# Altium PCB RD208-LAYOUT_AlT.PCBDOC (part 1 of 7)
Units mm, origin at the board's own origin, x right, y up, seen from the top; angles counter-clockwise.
Board outline 240 x 150 mm, 6 copper layers (TOP, Mid-Layer 1, Mid-Layer 2, Mid-Layer 3, Mid-Layer 4, BOTTOM), stack 1.422 mm thick; 773 components, 409 nets, 3936 pads, 97 vias.
Unrouted connection lines stored in the file: 1.
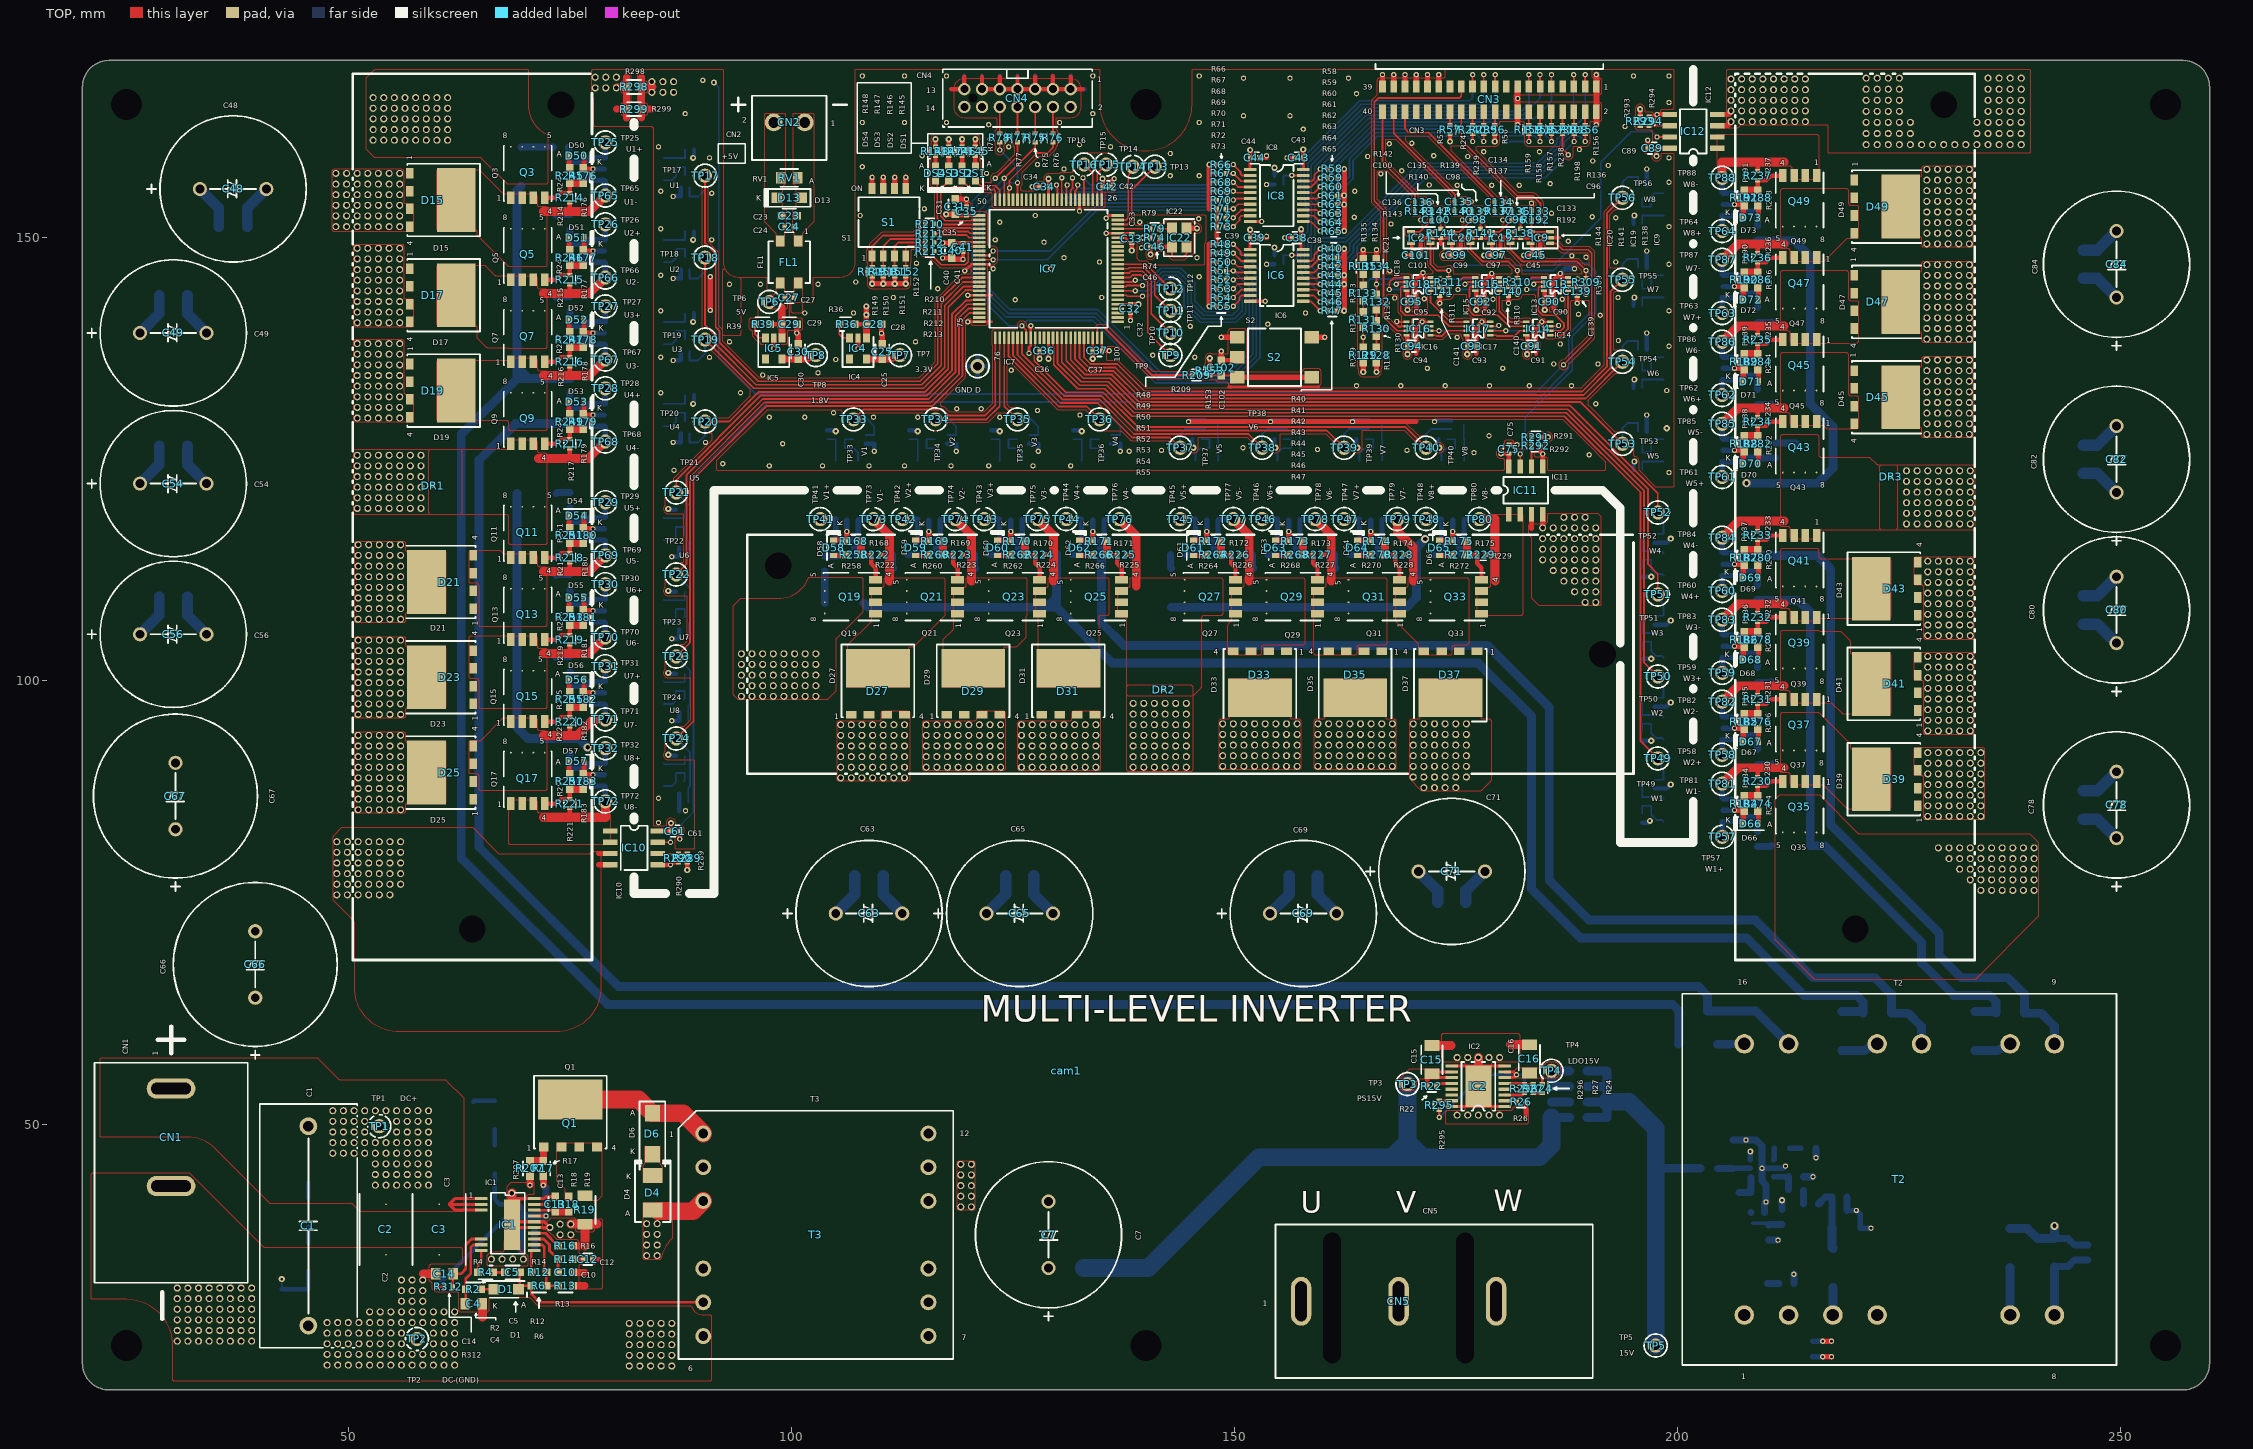
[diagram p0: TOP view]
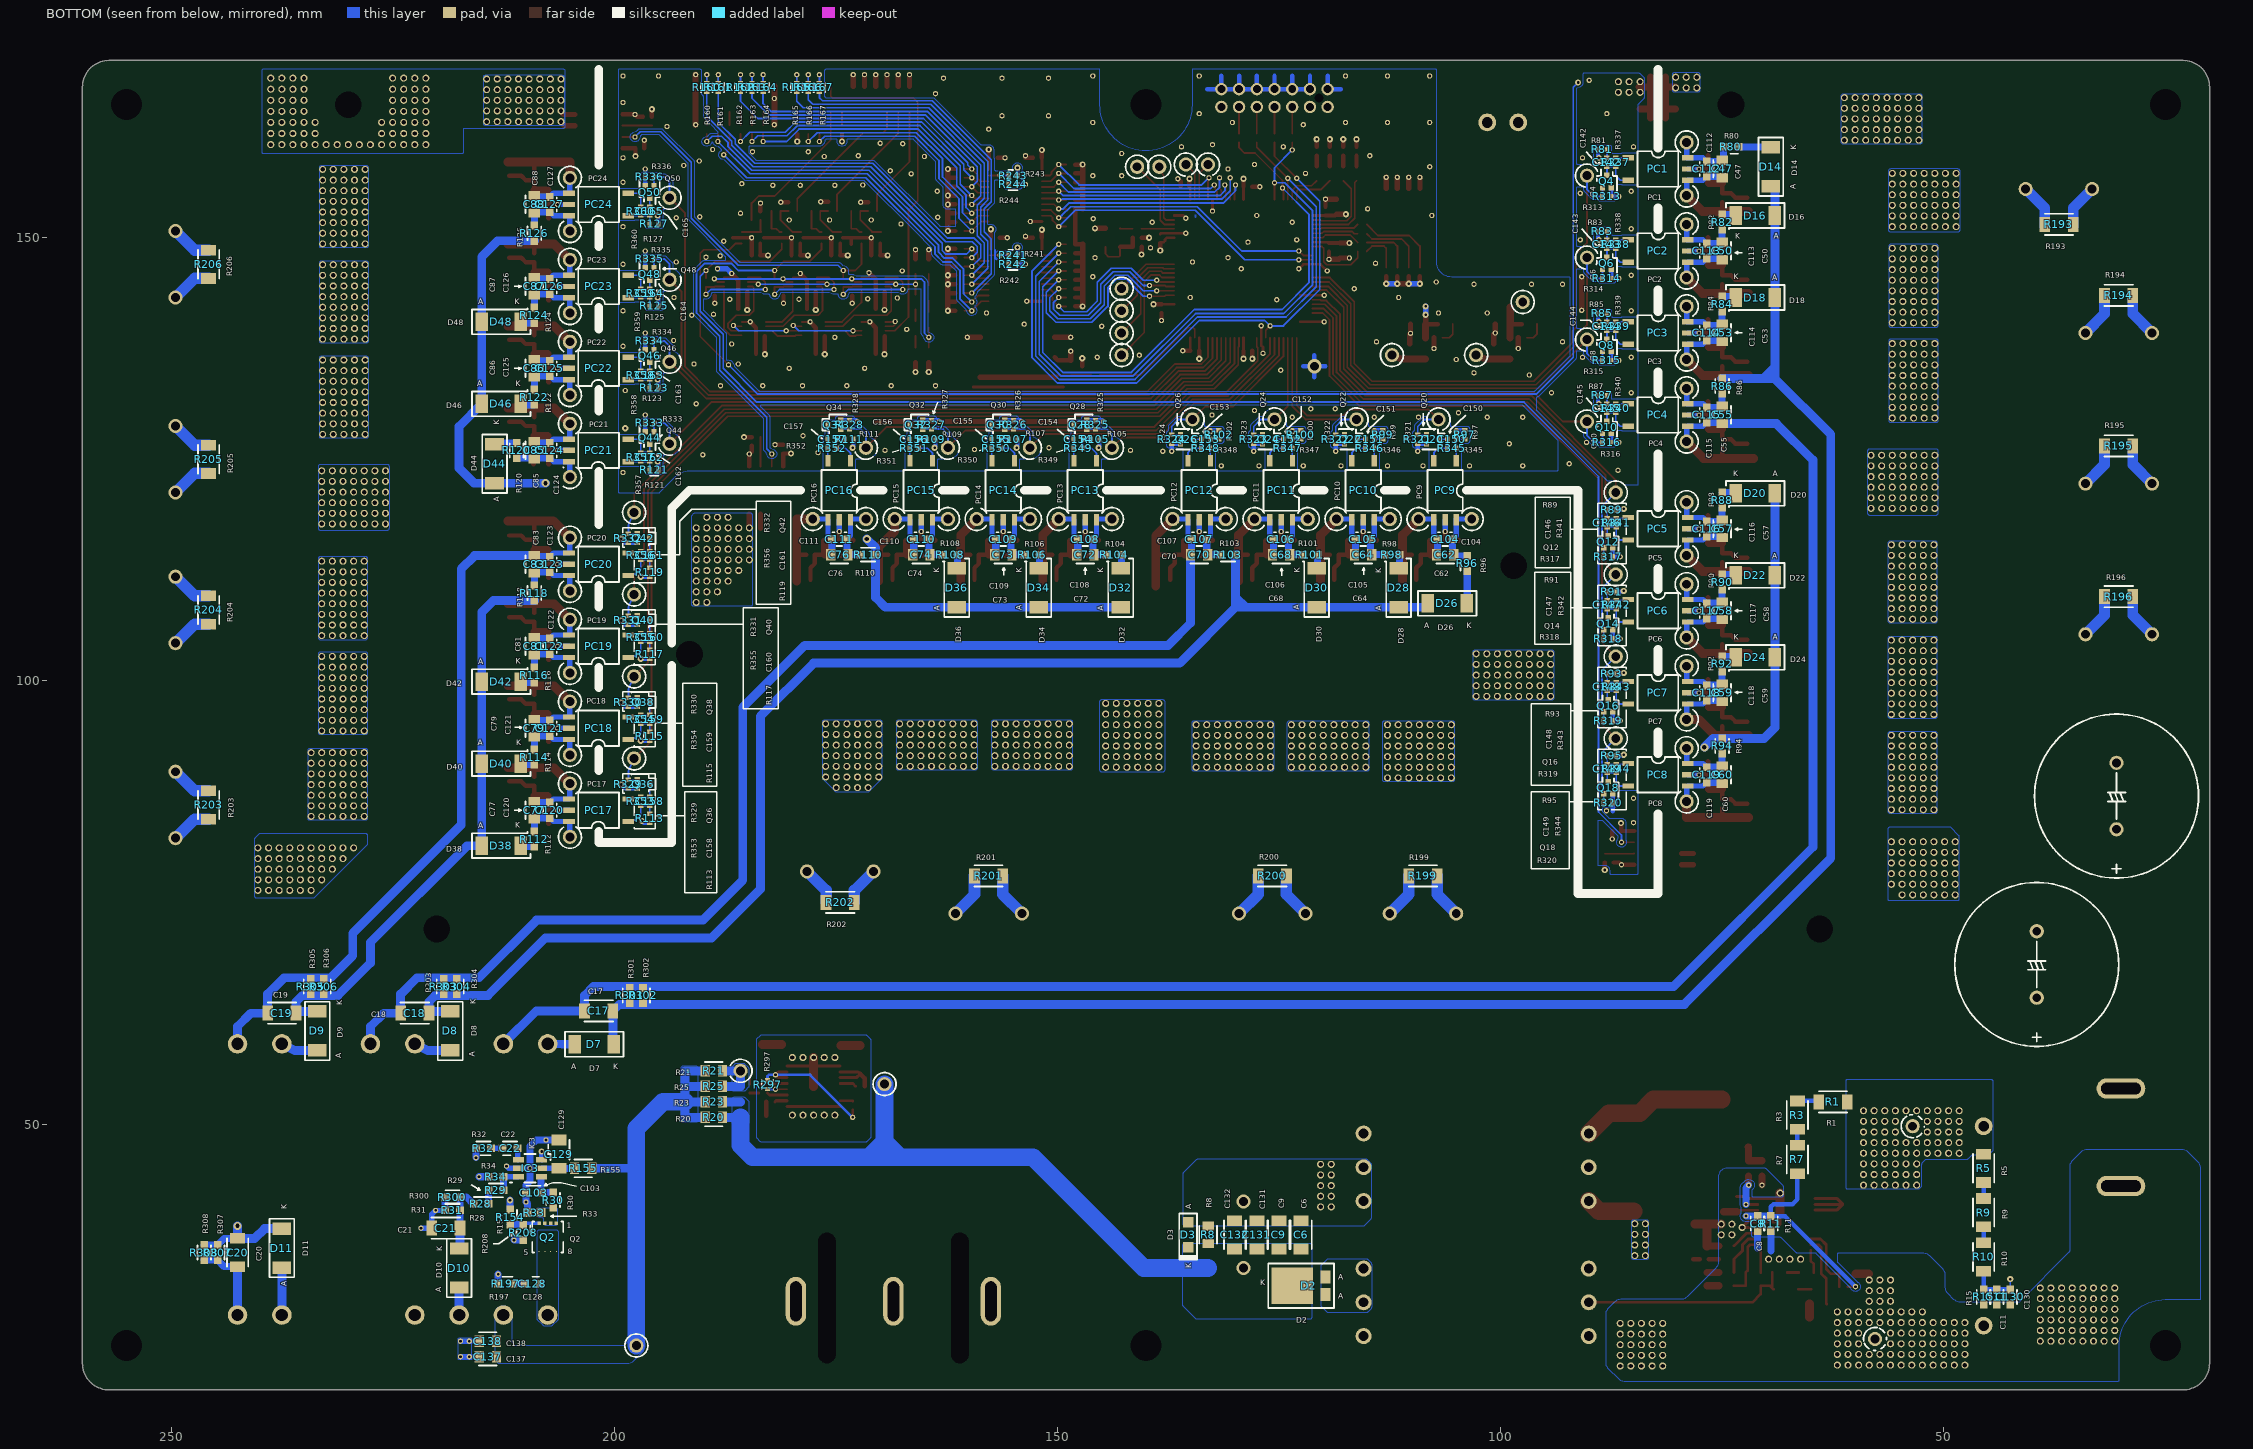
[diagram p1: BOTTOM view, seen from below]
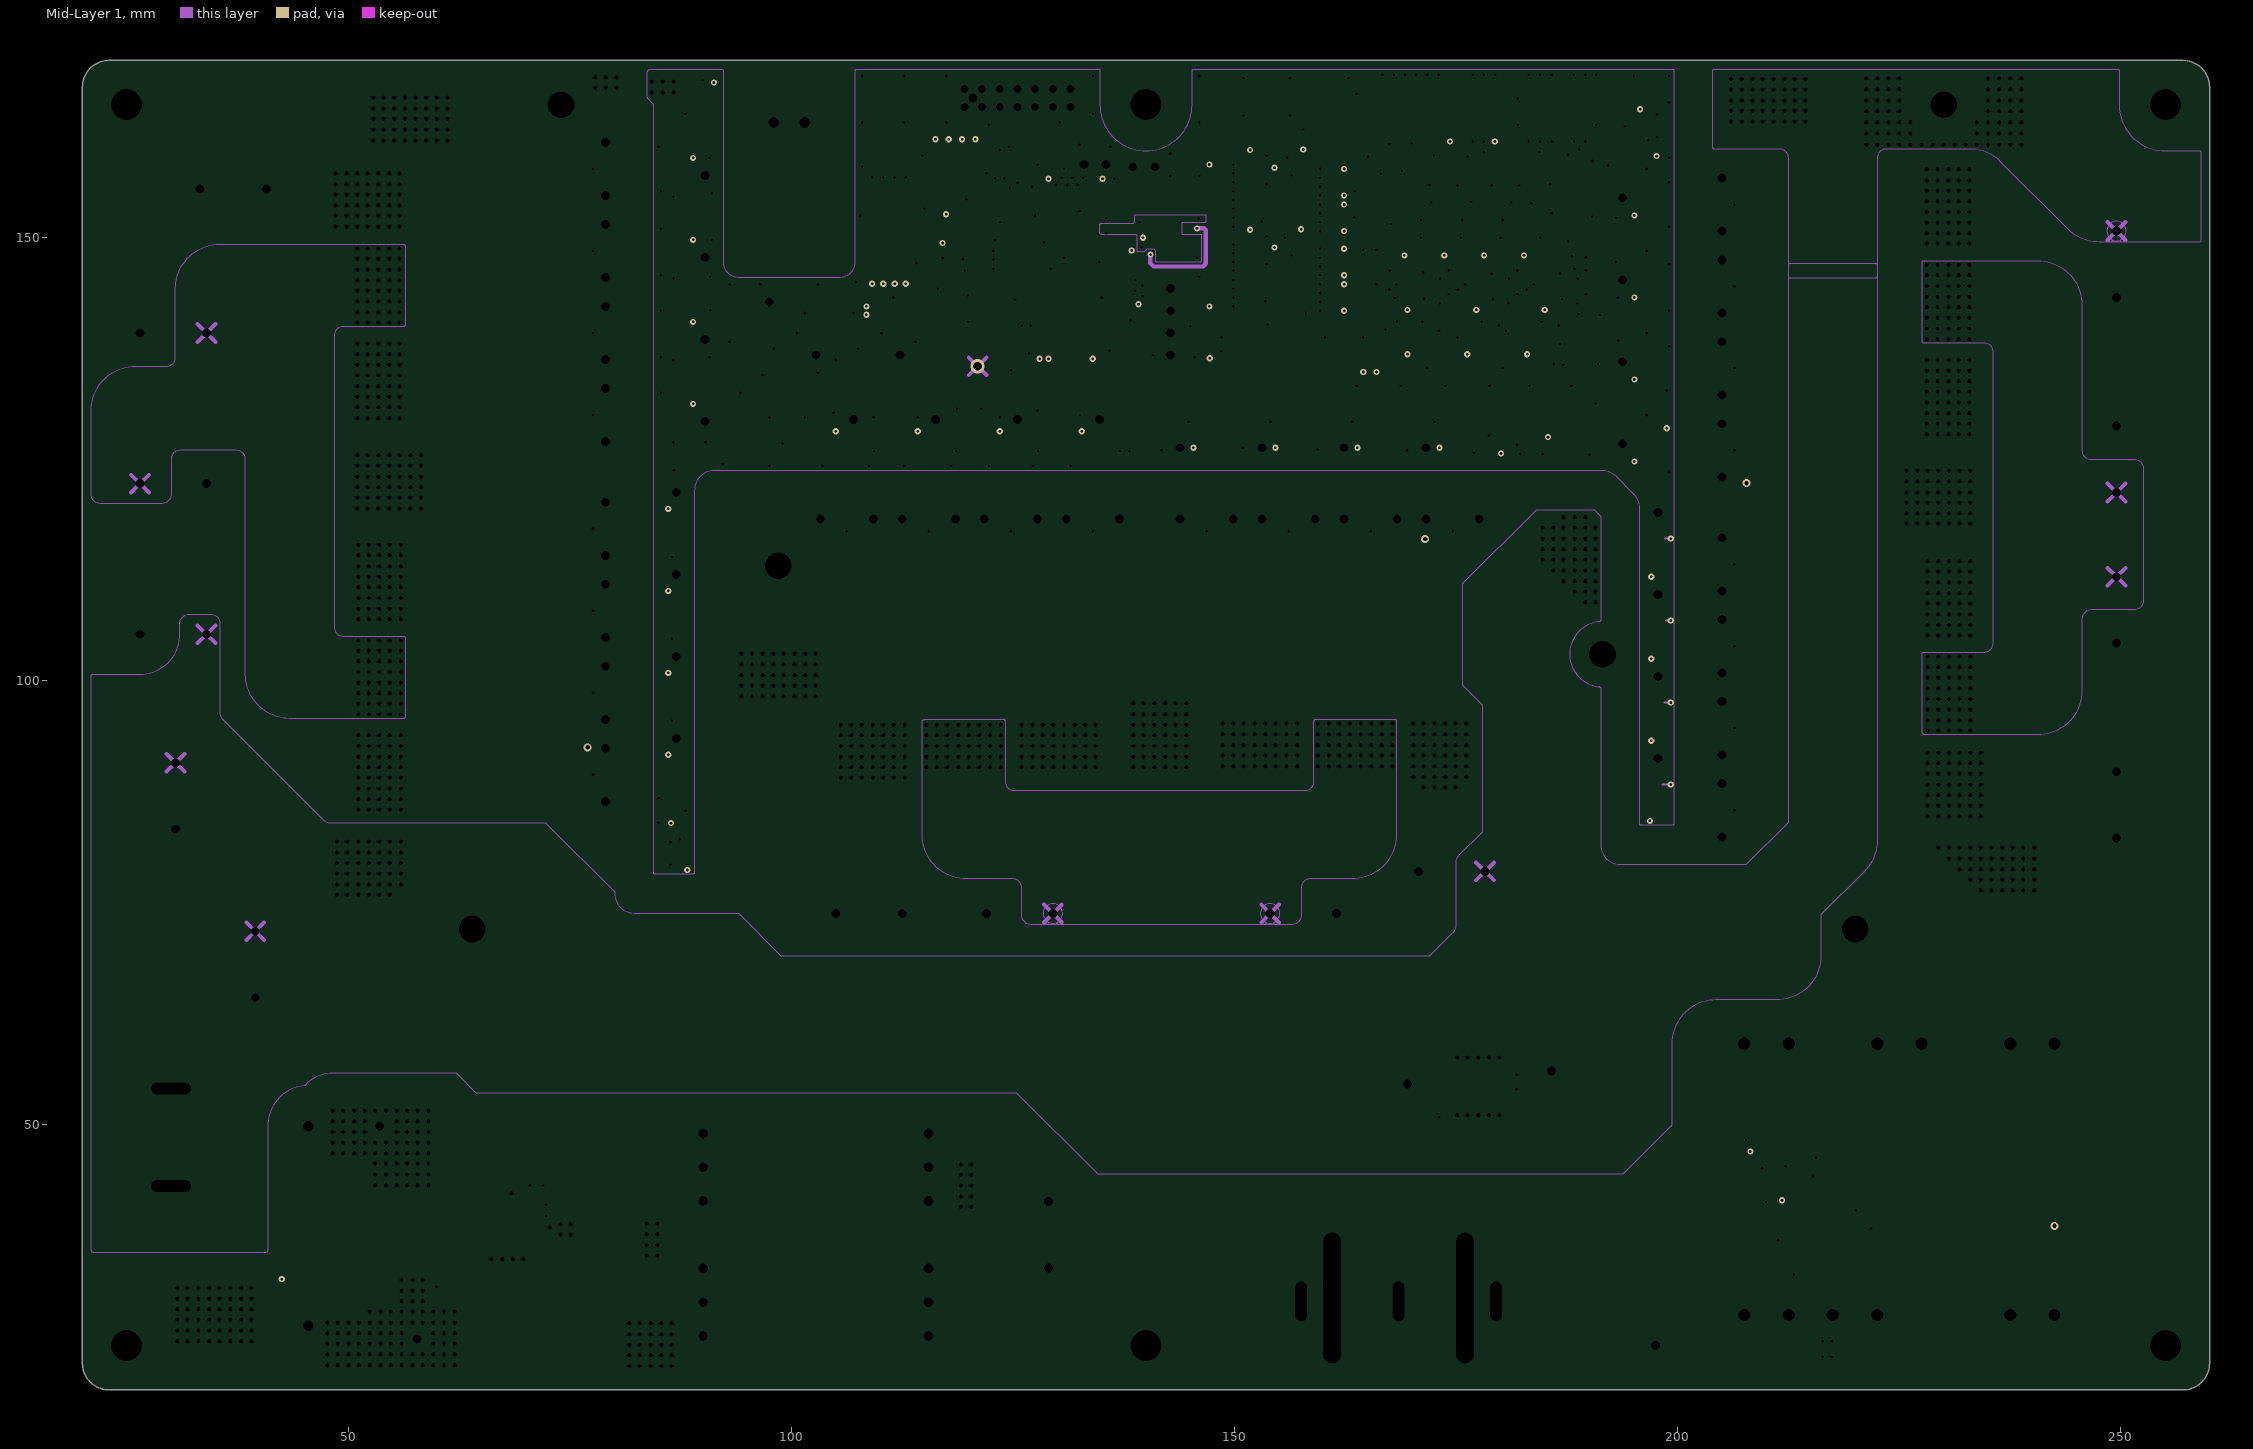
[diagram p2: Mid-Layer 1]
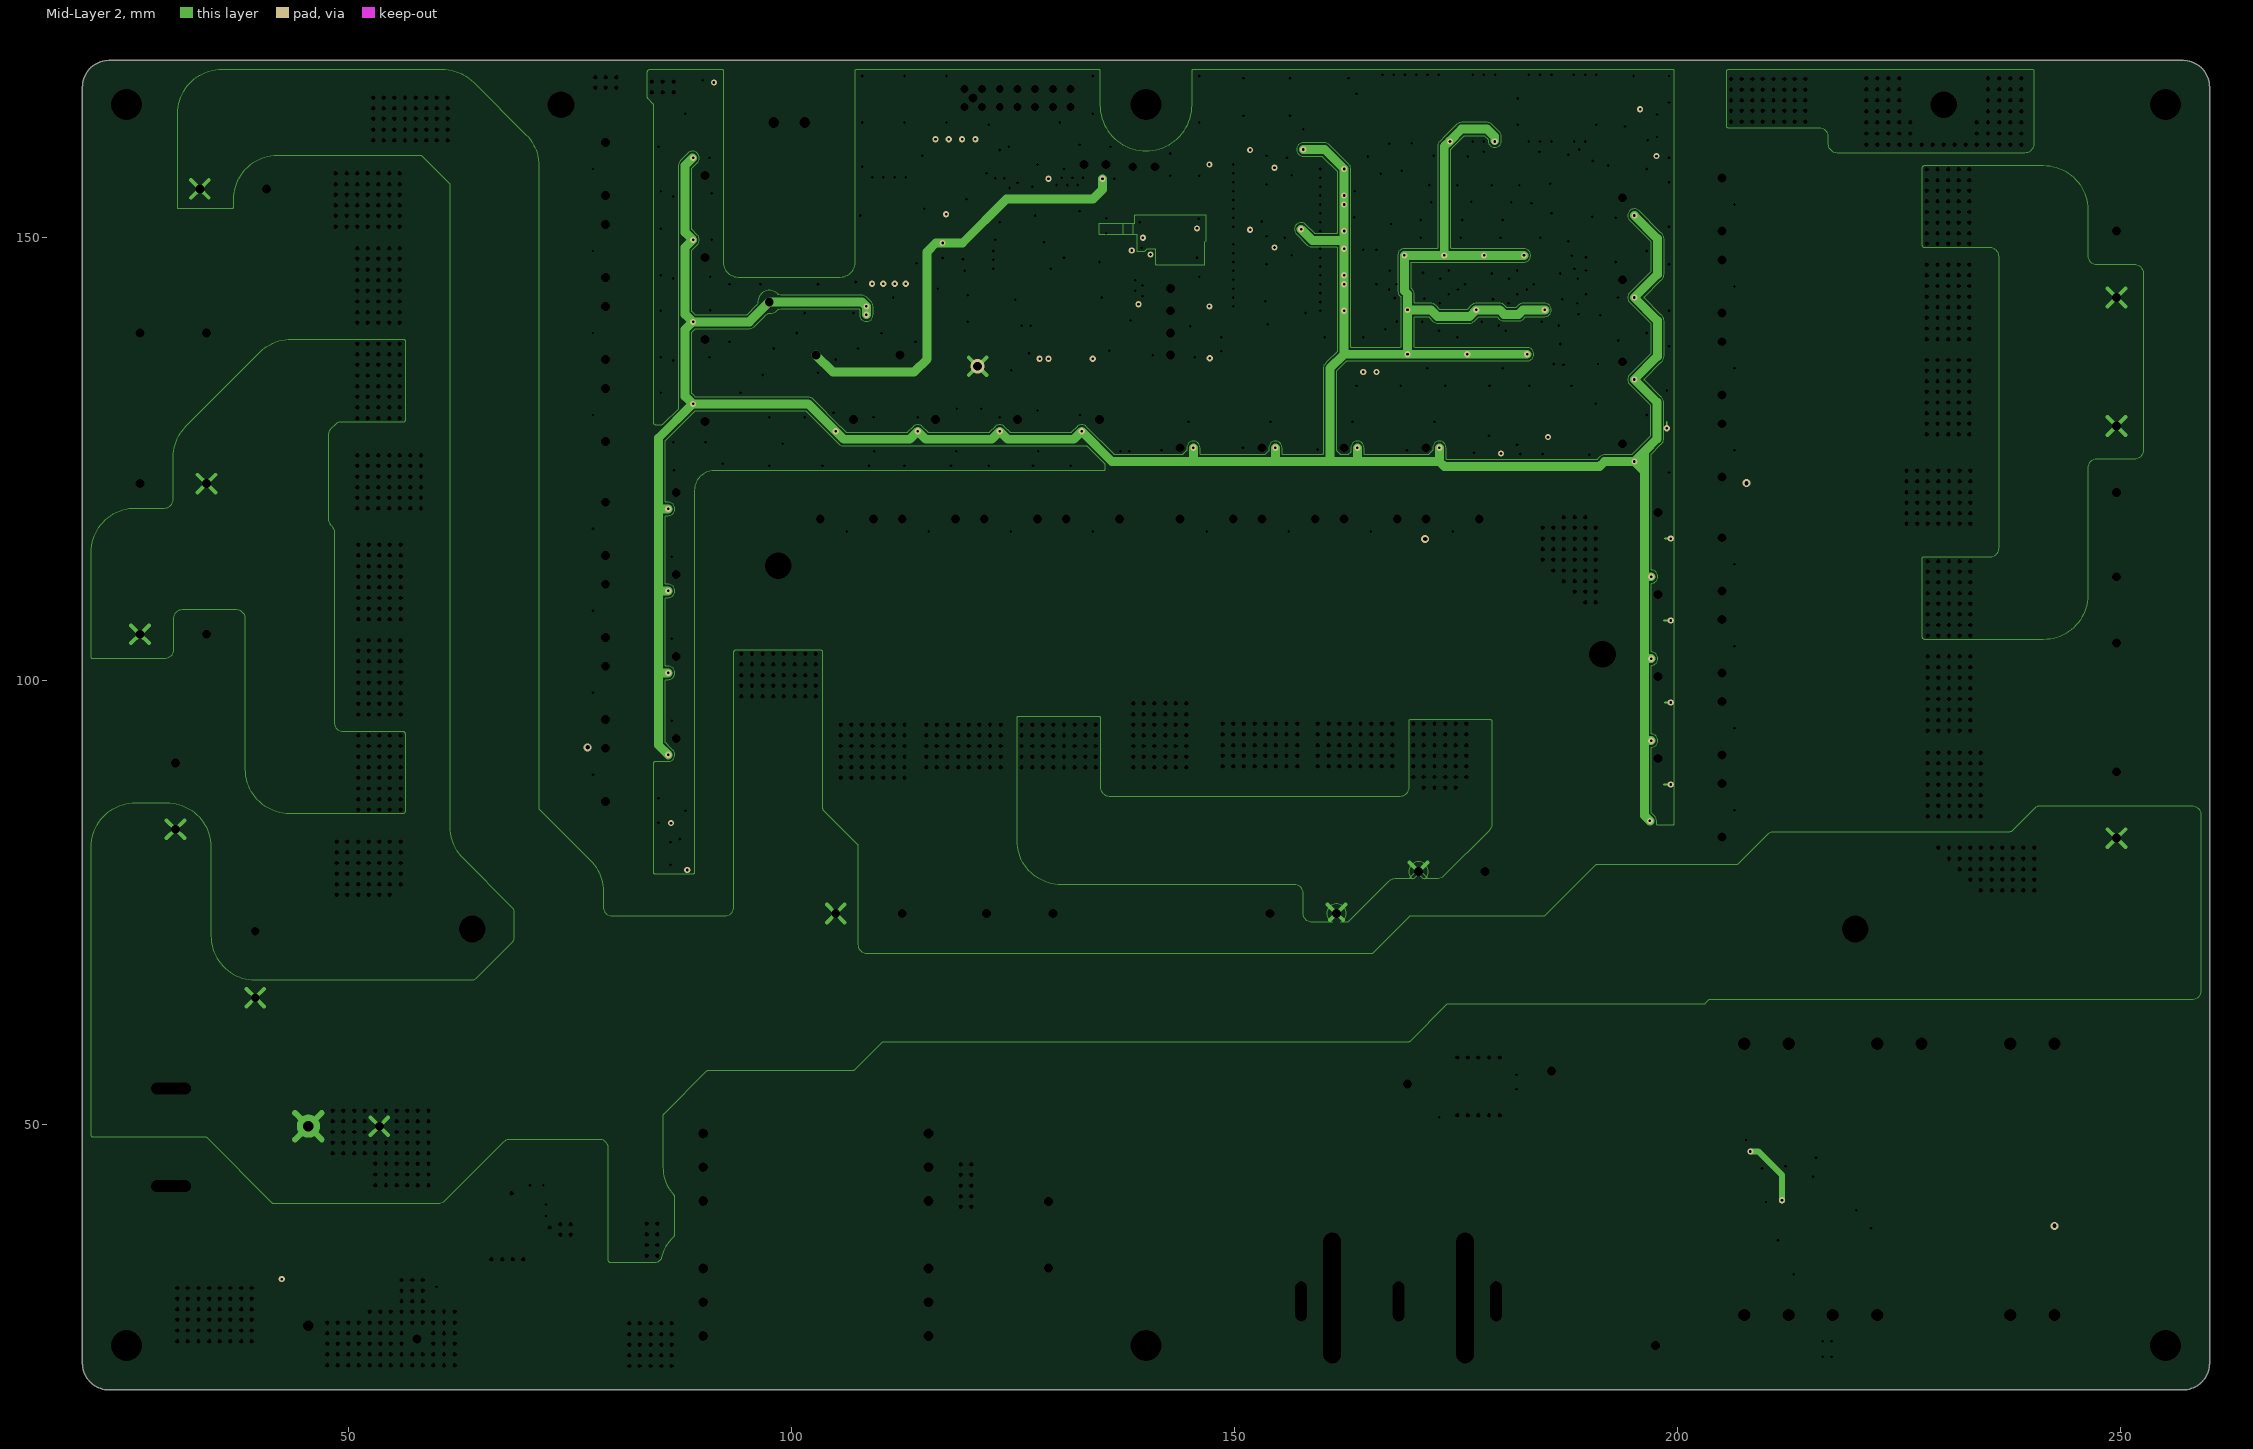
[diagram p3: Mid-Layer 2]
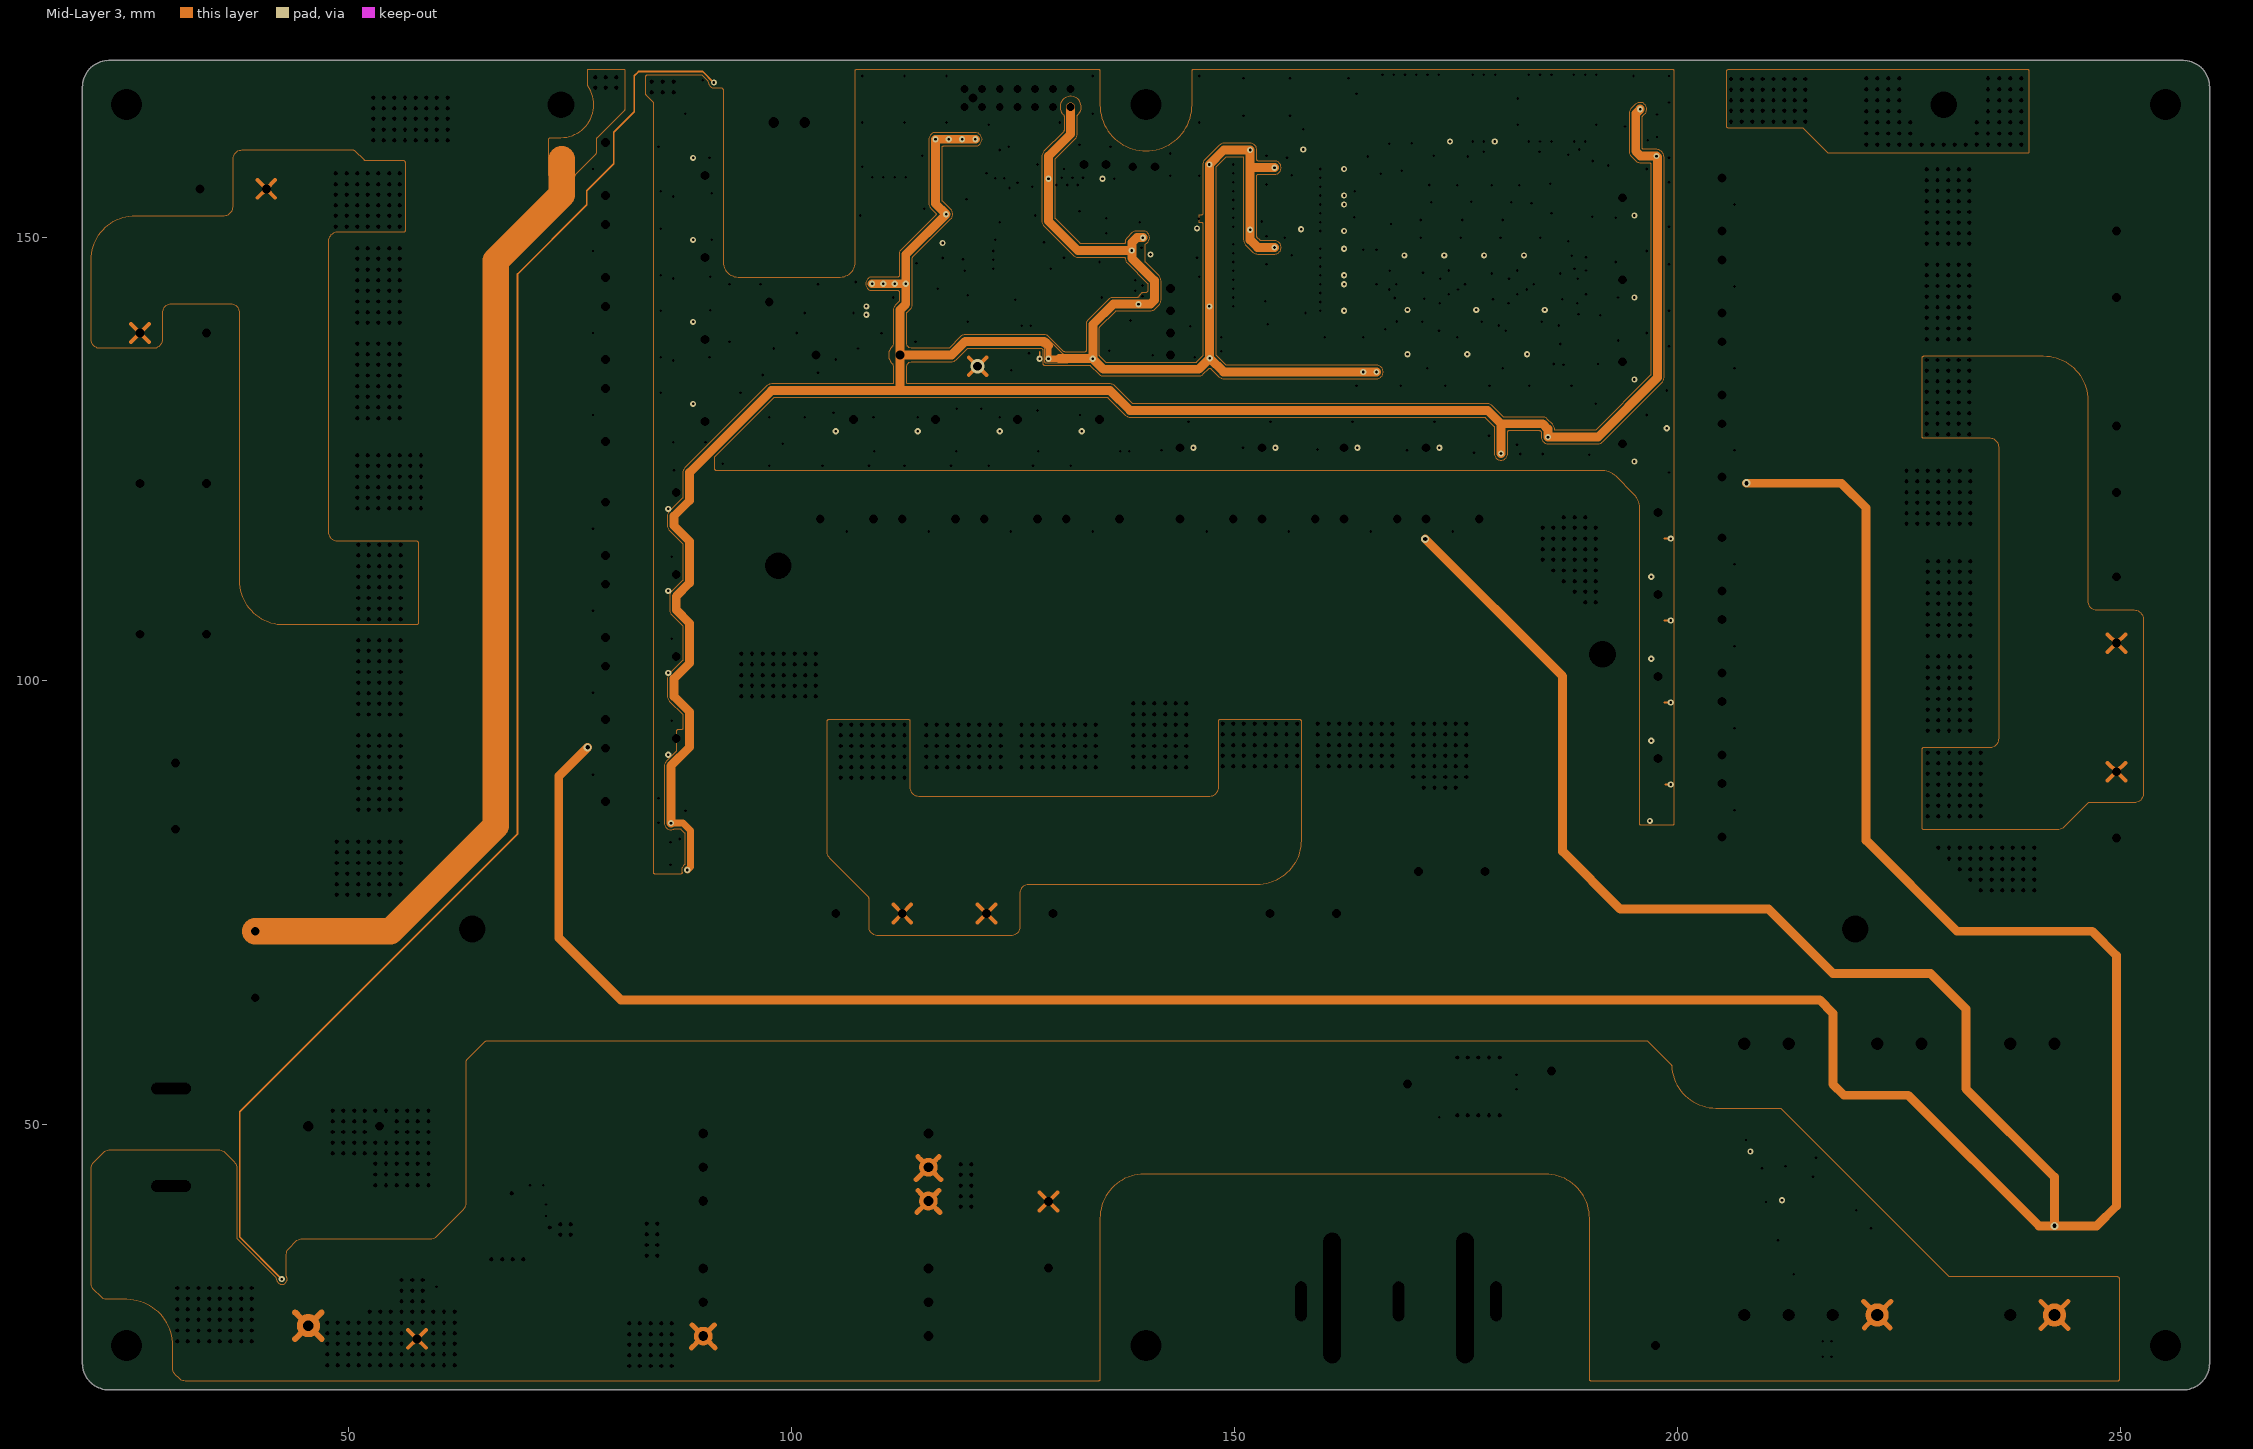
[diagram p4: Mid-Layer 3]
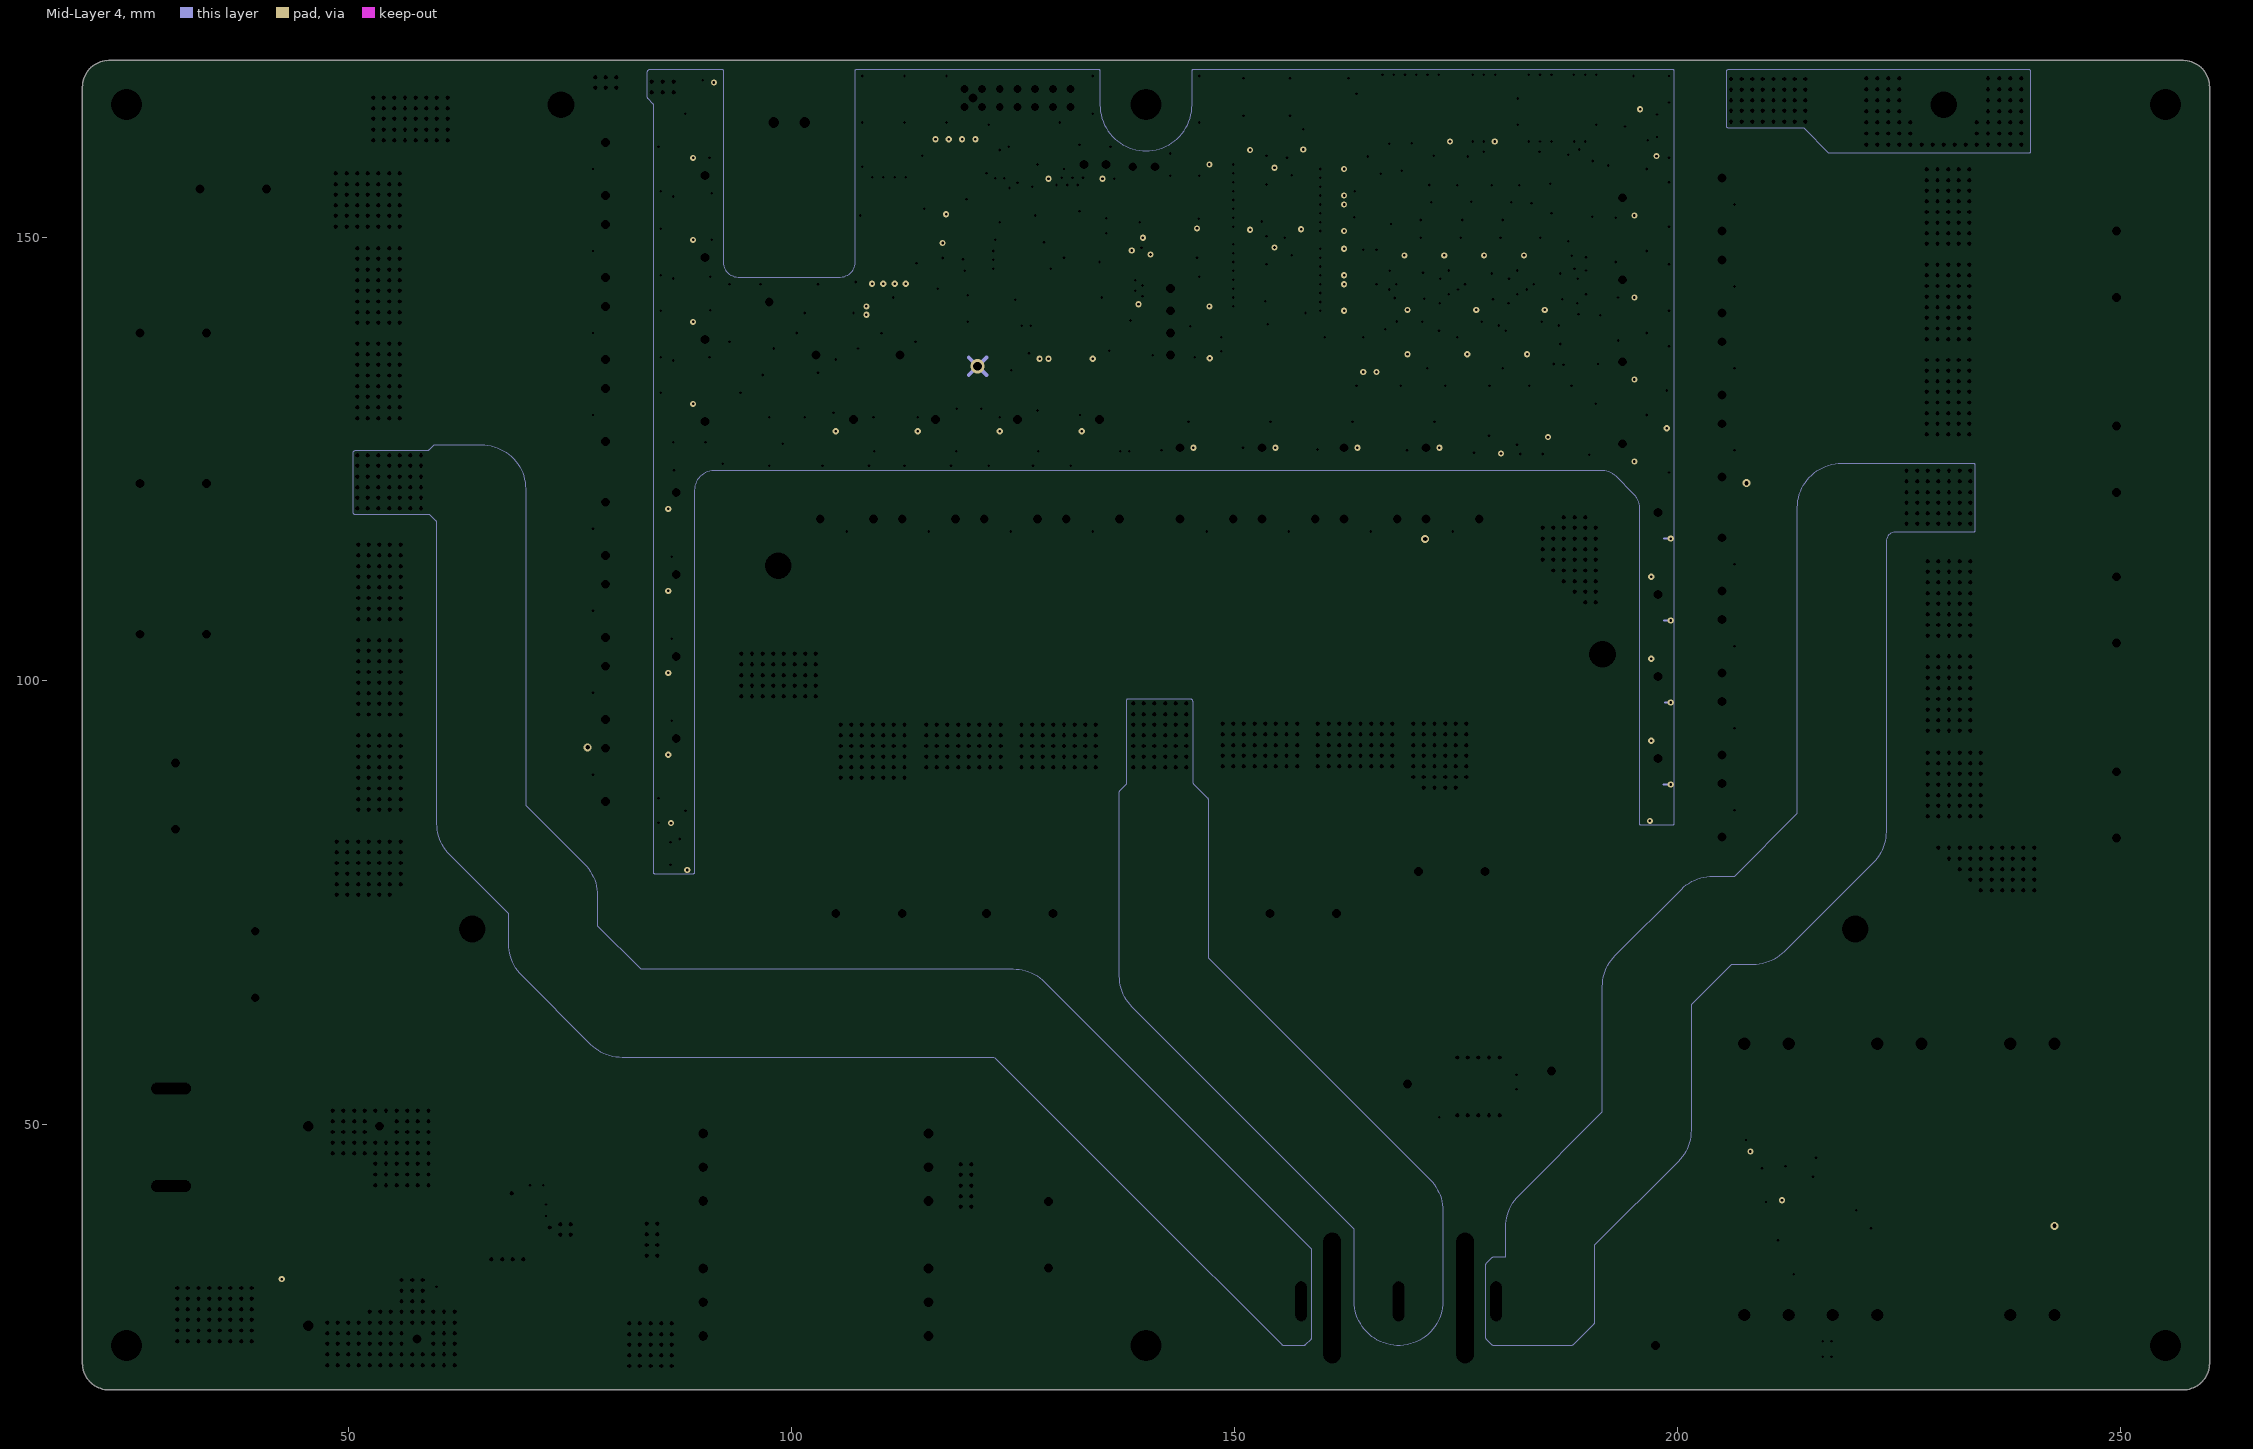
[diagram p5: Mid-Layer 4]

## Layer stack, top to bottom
Top Solder: solder mask 0.0102, Solder Resist, Dk 3.5
TOP: signal copper (thickness not stored)
Mid-Layer 1: signal copper 0.0356
Dielectric2: dielectric 0.32, FR-4, Dk 4.8
Mid-Layer 2: signal copper 0.0356
Dielectric3: dielectric 0.32, FR-4, Dk 4.8
Mid-Layer 3: signal copper 0.0356
Dielectric4: dielectric 0.32, FR-4, Dk 4.8
Mid-Layer 4: signal copper 0.0356
Dielectric5: dielectric 0.32, FR-4, Dk 4.8
BOTTOM: signal copper (thickness not stored)
Bottom Solder: solder mask 0.0102, Solder Resist, Dk 3.5

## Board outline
23,20 cw(c23,23) 20,23 20,167 cw(c23,167) 23,170 257,170 cw(c257,167) 260,167 260,23 cw(c257,23) 257,20

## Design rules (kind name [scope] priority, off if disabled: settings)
AssemblyTestPointUsage [All] p0: scope1count=1 scope1_0_kind=Board scope1_0_value=Board scope2count=1 scope2_0_kind=Board scope2_0_value=Board commentlength=0
AssemblyTestpoint [All] p0: scope1count=1 scope1_0_kind=Board scope1_0_value=Board scope2count=1 scope2_0_kind=Board scope2_0_value=Board commentlength=0
Clearance [All] p0: scope1count=1 scope1_0_kind=Board scope1_0_value=Board scope2count=1 scope2_0_kind=Board scope2_0_value=Board commentlength=0 gap=0.25
Clearance [All] p1: gap=0.25 ignorepadtopadclearanceinfootprint=TRUE except(0.2: Arc-Arc Arc-Track Arc-SMDPad Arc-THPad Arc-Via Arc-Text Track-Track Track-SMDPad Track-THPad Track-Via Track-Text SMDPad-Text THPad-Text Via-Text Text-Text; 0.3: SMDPad-Via Via-Via; 0.4: SMDPad-SMDPad SMDPad-THPad THPad-THPad THPad-Via; 0.5: Arc-Hole Track-Hole SMDPad-Hole THPad-Fill THPad-Poly THPad-Region THPad-Hole Via-Hole Fill-Hole Poly-Hole Region-Hole Text-Hole)
ComponentClearance [All] p0: scope1count=1 scope1_0_kind=Board scope1_0_value=Board scope2count=1 scope2_0_kind=Board scope2_0_value=Board commentlength=0 gap=0.254 collisioncheckmode=3
DiffPairsRouting [All] p0: scope1count=1 scope1_0_kind=Board scope1_0_value=Board scope2count=1 scope2_0_kind=Board scope2_0_value=Board commentlength=0
FabricationTestPointUsage [All] p0: scope1count=1 scope1_0_kind=Board scope1_0_value=Board scope2count=1 scope2_0_kind=Board scope2_0_value=Board commentlength=0 valid=0 allowmultiple=FALSE
FabricationTestpoint [All] p0: scope1count=1 scope1_0_kind=Board scope1_0_value=Board scope2count=1 scope2_0_kind=Board scope2_0_value=Board commentlength=0 side=3 testpointundercomponent=TRUE minsize=1.016 maxsize=2.54 preferedsize=1.524 minholesize=0 maxholesize=1.016 preferedholesize=0.813 testpointgrid=0.025
FanoutControl Fanout_BGA [All] p0 off: scope1count=1 scope1_0_kind=Board scope1_0_value=Board scope2count=1 scope2_0_kind=Board scope2_0_value=Board commentlength=69 // Protel DXP Scope 1 Expression Was: IsBGA   Fanout_BGA (Default Rule)
FanoutControl Fanout_LCC [All] p0 off: scope1count=1 scope1_0_kind=Board scope1_0_value=Board scope2count=1 scope2_0_kind=Board scope2_0_value=Board commentlength=69 // Protel DXP Scope 1 Expression Was: IsLCC   Fanout_LCC (Default Rule)
FanoutControl Fanout_SOIC [All] p0 off: scope1count=1 scope1_0_kind=Board scope1_0_value=Board scope2count=1 scope2_0_kind=Board scope2_0_value=Board commentlength=71 // Protel DXP Scope 1 Expression Was: IsSOIC   Fanout_SOIC (Default Rule)
FanoutControl Fanout_Small [All] p0 off: scope1count=1 scope1_0_kind=Board scope1_0_value=Board scope2count=1 scope2_0_kind=Board scope2_0_value=Board commentlength=84 // Protel DXP Scope 1 Expression Was: (CompPinCount < 5)   Fanout_Small (Default Rule)
FanoutControl Fanout_Default [All] p0: scope1count=1 scope1_0_kind=Board scope1_0_value=Board scope2count=1 scope2_0_kind=Board scope2_0_value=Board commentlength=30 // Fanout_Default (Default Rule)
Height [All] p0: scope1count=1 scope1_0_kind=Board scope1_0_value=Board scope2count=1 scope2_0_kind=Board scope2_0_value=Board commentlength=0
HoleSize [All] p0: scope1count=1 scope1_0_kind=Board scope1_0_value=Board scope2count=1 scope2_0_kind=Board scope2_0_value=Board commentlength=0 absolutevalues=TRUE maxlimit=100 minlimit=0.001 maxpercent=80.000 minpercent=20.000
HoleSize [All] p1: absolutevalues=TRUE maxlimit=100 minlimit=0.001 maxpercent=80.000 minpercent=20.000
HoleToHoleClearance [All] p0: scope1count=1 scope1_0_kind=Board scope1_0_value=Board scope2count=1 scope2_0_kind=Board scope2_0_value=Board commentlength=0
HoleToHoleClearance [All] p1: gap=0.5 allowstackedmicrovias=FALSE
LayerPairs [All] p0: scope1count=1 scope1_0_kind=Board scope1_0_value=Board scope2count=1 scope2_0_kind=Board scope2_0_value=Board commentlength=0 enforce=TRUE
MinimumSolderMaskSliver [All] p0: scope1count=1 scope1_0_kind=Board scope1_0_value=Board scope2count=1 scope2_0_kind=Board scope2_0_value=Board commentlength=0
MinimumSolderMaskSliver [All] p1: minsoldermaskwidth=0.2
NetAntennae [All] p0: scope1count=1 scope1_0_kind=Board scope1_0_value=Board scope2count=1 scope2_0_kind=Board scope2_0_value=Board commentlength=0
NetAntennae [All] p1: netantennaetolerance=100
PasteMaskExpansion [All] p0: scope1count=1 scope1_0_kind=Board scope1_0_value=Board scope2count=1 scope2_0_kind=Board scope2_0_value=Board commentlength=0 expansion=0
PlaneClearance [All] p0: scope1count=1 scope1_0_kind=Board scope1_0_value=Board scope2count=1 scope2_0_kind=Board scope2_0_value=Board commentlength=0 clearance=0.001
PlaneClearance [All] p1: clearance=0.001
PlaneConnect [All] p0: scope1count=1 scope1_0_kind=Board scope1_0_value=Board scope2count=1 scope2_0_kind=Board scope2_0_value=Board commentlength=0 planeconnectstyle=Direct reliefexpansion=0.508 reliefentries=4 reliefconductorwidth=0.254 reliefairgap=0.254
PlaneConnect [All] p1: planeconnectstyle=Direct reliefexpansion=0.508 reliefentries=4 reliefconductorwidth=0.254 reliefairgap=0.254
PolygonConnect [All] p0: scope1count=1 scope1_0_kind=Board scope1_0_value=Board scope2count=1 scope2_0_kind=Board scope2_0_value=Board commentlength=0 connectstyle=Direct reliefconductorwidth=0.254 reliefentries=4 polygonreliefangle="90 Angle"
PolygonConnect [All] p1: connectstyle=Direct reliefconductorwidth=0.254 reliefentries=4 polygonreliefangle="90 Angle" airgapwidth=0.254
RoutingCorners [All] p0: scope1count=1 scope1_0_kind=Board scope1_0_value=Board scope2count=1 scope2_0_kind=Board scope2_0_value=Board commentlength=0 cornerstyle=45-Degree minsetback=2.54 maxsetback=2.54
RoutingLayers [All] p0: scope1count=1 scope1_0_kind=Board scope1_0_value=Board scope2count=1 scope2_0_kind=Board scope2_0_value=Board commentlength=0 top layer=Automatic mid layer 1=Automatic mid layer 2=Automatic mid layer 3=Automatic mid layer 4=Automatic bottom layer=Automatic
RoutingPriority [All] p0: scope1count=1 scope1_0_kind=Board scope1_0_value=Board scope2count=1 scope2_0_kind=Board scope2_0_value=Board commentlength=0
RoutingTopology [All] p0: scope1count=1 scope1_0_kind=Board scope1_0_value=Board scope2count=1 scope2_0_kind=Board scope2_0_value=Board commentlength=0 topology=Shortest
RoutingVias [All] p0: scope1count=1 scope1_0_kind=Board scope1_0_value=Board scope2count=1 scope2_0_kind=Board scope2_0_value=Board commentlength=0 holewidth=0.1 width=0.1 viastyle="Through Hole" minholewidth=0.001 minwidth=0.001 maxholewidth=100 maxwidth=100
RoutingVias [All] p1: holewidth=0.1 width=0.1 viastyle="Through Hole" minholewidth=0.001 minwidth=0.001 maxholewidth=100 maxwidth=100
ShortCircuit [All] p0: scope1count=1 scope1_0_kind=Board scope1_0_value=Board scope2count=1 scope2_0_kind=Board scope2_0_value=Board commentlength=0 allowed=FALSE
SilkToBoardRegionClearance [All] p0: scope1count=1 scope1_0_kind=Board scope1_0_value=Board scope2count=1 scope2_0_kind=Board scope2_0_value=Board commentlength=0
SilkToSilkClearance [All] p0: scope1count=1 scope1_0_kind=Board scope1_0_value=Board scope2count=1 scope2_0_kind=Board scope2_0_value=Board commentlength=0
SilkToSilkClearance [All] p1: silktosilkclearance=0.001
SilkToSolderMaskClearance [All] p0 off: scope1count=1 scope1_0_kind=Board scope1_0_value=Board scope2count=1 scope2_0_kind=Board scope2_0_value=Board commentlength=44 // Protel DXP Scope 1 Expression Was: IsPad
SilkToSolderMaskClearance [IsPad] p1: minsilkscreentomaskgap=0.2 clearancetoexposedcopper=TRUE
SolderMaskExpansion [All] p0: scope1count=1 scope1_0_kind=Board scope1_0_value=Board scope2count=1 scope2_0_kind=Board scope2_0_value=Board commentlength=0 expansion=0.001
SolderMaskExpansion [All] p1: expansion=0.001
UnRoutedNet [All] p0: scope1count=1 scope1_0_kind=Board scope1_0_value=Board scope2count=1 scope2_0_kind=Board scope2_0_value=Board commentlength=0
UnpouredPolygon [All] p0: scope1count=1 scope1_0_kind=Board scope1_0_value=Board scope2count=1 scope2_0_kind=Board scope2_0_value=Board commentlength=0
Width [All] p0: scope1count=1 scope1_0_kind=Board scope1_0_value=Board scope2count=1 scope2_0_kind=Board scope2_0_value=Board commentlength=0 maxlimit=1000 minlimit=2539.975 preferedwidth=0
Width [All] p1: maxlimit=1000 minlimit=2539.975 preferedwidth=0 toplayer_minwidth=0 midlayer1_minwidth=0 midlayer2_minwidth=0 midlayer3_minwidth=0 midlayer4_minwidth=0 bottomlayer_minwidth=0 minimp=50.000000 maximp=50.000000 favimp=50.000000
22 further rules are at their usual default settings.

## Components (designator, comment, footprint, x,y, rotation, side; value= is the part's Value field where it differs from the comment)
C1 "C-27.0x10.5-P22.5-D-SP" C-27.0x10.5-P22.5-D-SP 45.5,38.5 r270 top
C2 "C5750-R-SP" C5750-R-SP 54.25,38.1 r270 top
C3 "C5750-R-SP" C5750-R-SP 60.25,38.1 r270 top
C4 "C2125_R_SP" C2125_R_SP#1 64.15,29.7 r0 top
C5 "C1608_R_SP" C1608_R_SP#1 68.5,33.25 r180 top
C6 "C3216-R-SP" C3216-R-SP#1 122.5,37.5 r270 bottom
C7 "CA-NICHEMI-D16.0-P7.5-D-SP" CA-NICHEMI-D16.0-P7.5-D-SP 129,37.5 r90 top
C8 "C1608_R_SP" C1608_R_SP#2 71,38.75 r270 bottom
C9 "C3216-R-SP" C3216-R-SP#1 125,37.5 r270 bottom
C10 "C1608_R_SP" C1608_R_SP#1 74.5,33.25 r0 top
C11 "C1608_R_SP" C1608_R_SP#2 44,30.5 r90 bottom
C12 "C1005_R_SP" C1005_R_SP#1 77,34.75 r0 top
C13 "C1608_R_SP" C1608_R_SP#1 73.35,40.95 r90 top
C14 "C2125_R_SP" C2125_R_SP#1 60.85,33.1 r180 top
C15 "C3216-R-SP" C3216-R-SP#2 172.25,57.25 r90 top
C16 "C3216-R-SP" C3216-R-SP#2 183.25,57.35 r90 top
C17 "C3216-R-SP" C3216-R-SP#1 201.75,62.75 r180 bottom
C18 "C3216-R-SP" C3216-R-SP#1 222.5,62.5 r180 bottom
C19 "C3216-R-SP" C3216-R-SP#1 237.5,62.5 r180 bottom
C20 "C3216-R-SP" C3216-R-SP#1 242.5,35.5 r90 bottom
C21 "C3216-R-SP" C3216-R-SP#1 219,38.25 r180 bottom
C22 "C1608_R_SP" C1608_R_SP#2 211.75,47.25 r180 bottom
C23 "C1608_R_SP" C1608_R_SP#1 99.75,152.5 r0 top
C24 "C1005_R_SP" C1005_R_SP#1 99.75,151.25 r0 top
C25 "C1608_R_SP" C1608_R_SP#1 110.25,137.15 r90 top
C27 "C1005_R_SP" C1005_R_SP#1 99.75,143.25 r0 top
C28 "C1608_R_SP" C1608_R_SP#1 109.3,140.25 r0 top
C29 "C1608_R_SP" C1608_R_SP#1 99.75,140.25 r0 top
C30 "C1608_R_SP" C1608_R_SP#1 100.75,137.15 r90 top
C31 "C1608_R_SP" C1608_R_SP#1 118.5,153.5 r90 top
C32 "C1005_R_SP" C1005_R_SP#1 138.25,142 r270 top
C33 "C1005_R_SP" C1005_R_SP#1 138.4,149.9 r90 top
C34 "C1005_R_SP" C1005_R_SP#1 128.5,155.75 r180 top
C35 "C1005_R_SP" C1005_R_SP#1 119.75,153 r90 top
C36 "C1005_R_SP" C1005_R_SP#1 128.5,137.25 r180 top
C37 "C1005_R_SP" C1005_R_SP#1 134.5,137.25 r0 top
C38 "C1005_R_SP" C1005_R_SP#1 157,150 r180 top
C39 "C1005_R_SP" C1005_R_SP#1 152.25,150 r0 top
C40 "C1608_R_SP" C1608_R_SP#1 118.1,148.55 r270 top
C41 "C1005_R_SP" C1005_R_SP#1 119.35,148.9 r270 top
C42 "C1005_R_SP" C1005_R_SP#1 135.6,155.75 r0 top
C43 "C1005_R_SP" C1005_R_SP#1 157.25,159 r180 top
C44 "C1005_R_SP" C1005_R_SP#1 152.25,159 r0 top
C45 "C1005_R_SP" C1005_R_SP#1 184,148 r0 top
C46 "C1005_R_SP" C1005_R_SP#1 141,149 r180 top
C47 "C2125_R_SP" C2125_R_SP#2 75,157.75 r90 bottom
C48 "CA-NICHEMI-D16.0-P7.5-D-SP" CA-NICHEMI-D16.0-P7.5-D-SP 37,155.5 r0 top
C49 "CA-NICHEMI-D16.0-P7.5-D-SP" CA-NICHEMI-D16.0-P7.5-D-SP 30.25,139.25 r0 top
C50 "C2125_R_SP" C2125_R_SP#2 75,148.5 r90 bottom
C53 "C2125_R_SP" C2125_R_SP#2 75,139.25 r90 bottom
C54 "CA-NICHEMI-D16.0-P7.5-D-SP" CA-NICHEMI-D16.0-P7.5-D-SP 30.25,122.25 r0 top
C55 "C2125_R_SP" C2125_R_SP#2 75,130 r90 bottom
C56 "CA-NICHEMI-D16.0-P7.5-D-SP" CA-NICHEMI-D16.0-P7.5-D-SP 30.25,105.25 r0 top
C57 "C2125_R_SP" C2125_R_SP#2 75,117.15 r90 bottom
C58 "C2125_R_SP" C2125_R_SP#2 75,107.9 r90 bottom
C59 "C2125_R_SP" C2125_R_SP#2 75,98.65 r90 bottom
C60 "C2125_R_SP" C2125_R_SP#2 75,89.4 r90 bottom
C61 "C1005_R_SP" C1005_R_SP#1 86.9,83.05 r0 top
C62 "C2125_R_SP" C2125_R_SP#2 106.25,114.25 r180 bottom
C63 "CA-NICHEMI-D16.0-P7.5-D-SP" CA-NICHEMI-D16.0-P7.5-D-SP 108.75,73.75 r0 top
C64 "C2125_R_SP" C2125_R_SP#2 115.5,114.25 r180 bottom
C65 "CA-NICHEMI-D16.0-P7.5-D-SP" CA-NICHEMI-D16.0-P7.5-D-SP 125.75,73.75 r0 top
C66 "CA-D18.0-P7.5-D-SP" CA-D18.0-P7.5-D-SP 39.5,68 r90 top
C67 "CA-D18.0-P7.5-D-SP" CA-D18.0-P7.5-D-SP 30.5,87 r90 top
C68 "C2125_R_SP" C2125_R_SP#2 124.75,114.25 r180 bottom
C69 "CA-NICHEMI-D16.0-P7.5-D-SP" CA-NICHEMI-D16.0-P7.5-D-SP 157.75,73.75 r0 top
C70 "C2125_R_SP" C2125_R_SP#2 134,114.25 r180 bottom
C71 "CA-NICHEMI-D16.0-P7.5-D-SP" CA-NICHEMI-D16.0-P7.5-D-SP 174.5,78.5 r0 top
C72 "C2125_R_SP" C2125_R_SP#2 146.85,114.25 r180 bottom
C73 "C2125_R_SP" C2125_R_SP#2 156.1,114.25 r180 bottom
C74 "C2125_R_SP" C2125_R_SP#2 165.35,114.25 r180 bottom
C75 "C1005_R_SP" C1005_R_SP#1 180.95,126.15 r90 top
C76 "C2125_R_SP" C2125_R_SP#2 174.6,114.25 r180 bottom
C77 "C2125_R_SP" C2125_R_SP#2 209,85.4 r270 bottom
C78 "CA-NICHEMI-D16.0-P7.5-D-SP" CA-NICHEMI-D16.0-P7.5-D-SP 249.5,86 r90 top
C79 "C2125_R_SP" C2125_R_SP#2 209,94.65 r270 bottom
C80 "CA-NICHEMI-D16.0-P7.5-D-SP" CA-NICHEMI-D16.0-P7.5-D-SP 249.5,108 r90 top
C81 "C2125_R_SP" C2125_R_SP#2 209,103.9 r270 bottom
C82 "CA-NICHEMI-D16.0-P7.5-D-SP" CA-NICHEMI-D16.0-P7.5-D-SP 249.5,125 r90 top
C83 "C2125_R_SP" C2125_R_SP#2 209,113.15 r270 bottom
C84 "CA-NICHEMI-D16.0-P7.5-D-SP" CA-NICHEMI-D16.0-P7.5-D-SP 249.5,147 r90 top
C85 "C2125_R_SP" C2125_R_SP#2 209,126 r270 bottom
C86 "C2125_R_SP" C2125_R_SP#2 209,135.25 r270 bottom
C87 "C2125_R_SP" C2125_R_SP#2 209,144.5 r270 bottom
C88 "C2125_R_SP" C2125_R_SP#2 209,153.75 r270 bottom
C89 "C1005_R_SP" C1005_R_SP#1 197.1,160.1 r180 top
C90 "C1005_R_SP" C1005_R_SP#1 185.5,142.75 r0 top
C91 "C1005_R_SP" C1005_R_SP#1 183.5,137.75 r0 top
C92 "C1005_R_SP" C1005_R_SP#1 177.75,142.75 r0 top
C93 "C1005_R_SP" C1005_R_SP#1 176.75,137.75 r0 top
C94 "C1005_R_SP" C1005_R_SP#1 170,137.75 r0 top
C95 "C1005_R_SP" C1005_R_SP#1 170,142.75 r0 top
C96 "C1005_R_SP" C1005_R_SP#1 181.75,152 r0 top
C97 "C1005_R_SP" C1005_R_SP#1 179.5,148 r0 top
C98 "C1005_R_SP" C1005_R_SP#1 177.25,152 r0 top
C99 "C1005_R_SP" C1005_R_SP#1 175,148 r0 top
C100 "C1005_R_SP" C1005_R_SP#1 172.75,152 r0 top
C101 "C1005_R_SP" C1005_R_SP#1 170.5,148 r0 top
C102 "C1608_R_SP" C1608_R_SP#1 148.5,135.3 r90 top
C103 "C1608_R_SP" C1608_R_SP#2 209.1,42.25 r180 bottom
C104 "C1608_R_SP" C1608_R_SP#2 106.25,116 r180 bottom
C105 "C1608_R_SP" C1608_R_SP#2 115.5,116 r180 bottom
C106 "C1608_R_SP" C1608_R_SP#2 124.75,116 r180 bottom
C107 "C1608_R_SP" C1608_R_SP#2 134,116 r180 bottom
C108 "C1608_R_SP" C1608_R_SP#2 146.85,116 r180 bottom
C109 "C1608_R_SP" C1608_R_SP#2 156.1,116 r180 bottom
C110 "C1608_R_SP" C1608_R_SP#2 165.35,116 r180 bottom
C111 "C1608_R_SP" C1608_R_SP#2 174.6,116 r180 bottom
C112 "C1608_R_SP" C1608_R_SP#2 76.75,157.75 r90 bottom
C113 "C1608_R_SP" C1608_R_SP#2 76.75,148.5 r90 bottom
C114 "C1608_R_SP" C1608_R_SP#2 76.75,139.25 r90 bottom
C115 "C1608_R_SP" C1608_R_SP#2 76.75,130 r90 bottom
C116 "C1608_R_SP" C1608_R_SP#2 76.75,117.15 r90 bottom
C117 "C1608_R_SP" C1608_R_SP#2 76.75,107.9 r90 bottom
C118 "C1608_R_SP" C1608_R_SP#2 76.75,98.65 r90 bottom
C119 "C1608_R_SP" C1608_R_SP#2 76.75,89.4 r90 bottom
C120 "C1608_R_SP" C1608_R_SP#2 207.25,85.4 r270 bottom
C121 "C1608_R_SP" C1608_R_SP#2 207.25,94.65 r270 bottom
C122 "C1608_R_SP" C1608_R_SP#2 207.25,103.9 r270 bottom
C123 "C1608_R_SP" C1608_R_SP#2 207.25,113.15 r270 bottom
C124 "C1608_R_SP" C1608_R_SP#2 207.25,126 r270 bottom
C125 "C1608_R_SP" C1608_R_SP#2 207.25,135.25 r270 bottom
C126 "C1608_R_SP" C1608_R_SP#2 207.25,144.5 r270 bottom
C127 "C1608_R_SP" C1608_R_SP#2 207.25,153.75 r270 bottom
C128 "C1608_R_SP" C1608_R_SP#2 209.25,32 r180 bottom
C129 "C3216-R-SP" C3216-R-SP#1 206.25,46.6 r270 bottom
C130 "C1608_R_SP" C1608_R_SP#2 42.5,30.5 r90 bottom
C131 "C3216-R-SP" C3216-R-SP#1 127.5,37.5 r270 bottom
C132 "C3216-R-SP" C3216-R-SP#1 130,37.5 r270 bottom
C133 "C1005_R_SP" C1005_R_SP#1 184,153 r180 top
C134 "C1005_R_SP" C1005_R_SP#1 179.85,154 r0 top
C135 "C1005_R_SP" C1005_R_SP#1 175.35,154.05 r0 top
C136 "C1005_R_SP" C1005_R_SP#1 170.85,154 r0 top
C137 "C2125_R_SP" C2125_R_SP#2 214.25,23.75 r180 bottom
C138 "C2125_R_SP" C2125_R_SP#2 214.25,25.5 r180 bottom
C139 "C1005_R_SP" C1005_R_SP#1 188.65,143.95 r270 top
C140 "C1005_R_SP" C1005_R_SP#1 180.9,143.95 r270 top
C141 "C1005_R_SP" C1005_R_SP#1 173.15,143.95 r270 top
C142 "C1005_R_SP" C1005_R_SP#2 88,158.5 r90 bottom
C143 "C1005_R_SP" C1005_R_SP#2 88,149.25 r90 bottom
C144 "C1005_R_SP" C1005_R_SP#2 88,140 r90 bottom
C145 "C1005_R_SP" C1005_R_SP#2 88,130.75 r90 bottom
C146 "C1005_R_SP" C1005_R_SP#2 87.95,117.85 r90 bottom
C147 "C1005_R_SP" C1005_R_SP#2 87.95,108.6 r90 bottom
C148 "C1005_R_SP" C1005_R_SP#2 87.95,99.35 r90 bottom
C149 "C1005_R_SP" C1005_R_SP#2 87.95,90.1 r90 bottom
C150 "C1005_R_SP" C1005_R_SP#2 105.5,127.25 r180 bottom
C151 "C1005_R_SP" C1005_R_SP#2 114.75,127.25 r180 bottom
C152 "C1005_R_SP" C1005_R_SP#2 124,127.25 r180 bottom
C153 "C1005_R_SP" C1005_R_SP#2 133.25,127.25 r180 bottom
C154 "C1005_R_SP" C1005_R_SP#2 147.65,127.25 r180 bottom
C155 "C1005_R_SP" C1005_R_SP#2 156.9,127.25 r180 bottom
C156 "C1005_R_SP" C1005_R_SP#2 166.15,127.25 r180 bottom
C157 "C1005_R_SP" C1005_R_SP#2 175.4,127.25 r180 bottom
C158 "C1005_R_SP" C1005_R_SP#2 196,86.4 r270 bottom
C159 "C1005_R_SP" C1005_R_SP#2 196,95.65 r270 bottom
C160 "C1005_R_SP" C1005_R_SP#2 196,104.9 r270 bottom
C161 "C1005_R_SP" C1005_R_SP#2 196,114.15 r270 bottom
C162 "C1005_R_SP" C1005_R_SP#2 196,125.25 r270 bottom
C163 "C1005_R_SP" C1005_R_SP#2 196,134.5 r270 bottom
C164 "C1005_R_SP" C1005_R_SP#2 196,143.75 r270 bottom
C165 "C1005_R_SP" C1005_R_SP#2 196,153 r270 bottom
cam1 "S_LOGO_TOSHIBA" S_LOGO_TOSHIBA 131,56 r0 top
CN1 "OTB-640NS-B-2P-C-D-SP" OTB-640NS-B-2P-C-D-SP 30,54 r270 top
CN2 "1843606-D-SP" 1843606-D-SP 99.75,163 r0 top
CN3 "FTSH-120-04-x-DH-A-AEP-R-SP" FTSH-120-04-x-DH-A-AEP-R-SP 178.75,170.45 r0 top
CN4 "878311420-D-SP" 878311420-D-SP 125.5,165.75 r180 top
CN5 "OTB-640NS-B-3P-C-D-SP" OTB-640NS-B-3P-C-D-SP 157.5,30 r0 top
D1 "TO-3-2A1A-12-R-SP" TO-3-2A1A-12-R-SP 67.8,31.35 r180 top
D2 "ON-TO-227-3LD-123-R-SP" ON-TO-227-3LD-123-R-SP 122.5,31.75 r0 bottom
D3 "TO-3-2A1S-R-SP" TO-3-2A1S-R-SP#1 135.25,37.5 r90 bottom
D4 "VISHAY-DO-214AA-R-SP" VISHAY-DO-214AA-R-SP 84.35,42.25 r90 top
D6 "DIODES-D-FLAT-R-SP" DIODES-D-FLAT-R-SP 84.3,48.9 r270 top
D7 "TO-3-4E1A-R-SP" TO-3-4E1A-R-SP 202.25,59 r0 bottom
D8 "TO-3-4E1A-R-SP" TO-3-4E1A-R-SP 218.5,60.5 r270 bottom
D9 "TO-3-4E1A-R-SP" TO-3-4E1A-R-SP 233.5,60.5 r270 bottom
D10 "TO-3-4E1A-R-SP" TO-3-4E1A-R-SP 217.5,33.75 r270 bottom
D11 "TO-3-4E1A-R-SP" TO-3-4E1A-R-SP 237.5,36 r270 bottom
D13 "TO-3-2A1S-R-SP" TO-3-2A1S-R-SP#2 99.75,154.5 r180 top
D14 "TO-3-4E1S-R-SP" TO-3-4E1S-R-SP 69.5,158 r270 bottom
D15 "ON-PQFN4-8x8-2P-R-SP" ON-PQFN4-8x8-2P-R-SP 60.75,154.25 r270 top
D16 "TO-3-4E1S-R-SP" TO-3-4E1S-R-SP 71.25,152.5 r180 bottom
D17 "ON-PQFN4-8x8-2P-R-SP" ON-PQFN4-8x8-2P-R-SP 60.75,143.5 r270 top
D18 "TO-3-4E1S-R-SP" TO-3-4E1S-R-SP 71.25,143.25 r180 bottom
D19 "ON-PQFN4-8x8-2P-R-SP" ON-PQFN4-8x8-2P-R-SP 60.75,132.75 r270 top
D20 "TO-3-4E1S-R-SP" TO-3-4E1S-R-SP 71.25,121.15 r180 bottom
D21 "ON-PQFN4-8x8-2P-R-SP" ON-PQFN4-8x8-2P-R-SP 60.25,111.15 r90 top
D22 "TO-3-4E1S-R-SP" TO-3-4E1S-R-SP 71.25,111.9 r180 bottom
D23 "ON-PQFN4-8x8-2P-R-SP" ON-PQFN4-8x8-2P-R-SP 60.25,100.4 r90 top
D24 "TO-3-4E1S-R-SP" TO-3-4E1S-R-SP 71.25,102.65 r180 bottom
D25 "ON-PQFN4-8x8-2P-R-SP" ON-PQFN4-8x8-2P-R-SP 60.25,89.65 r90 top
D26 "TO-3-4E1S-R-SP" TO-3-4E1S-R-SP 106,108.75 r0 bottom
D27 "ON-PQFN4-8x8-2P-R-SP" ON-PQFN4-8x8-2P-R-SP 109.75,100 r0 top
D28 "TO-3-4E1S-R-SP" TO-3-4E1S-R-SP 111.5,110.5 r270 bottom
D29 "ON-PQFN4-8x8-2P-R-SP" ON-PQFN4-8x8-2P-R-SP 120.5,100 r0 top
D30 "TO-3-4E1S-R-SP" TO-3-4E1S-R-SP 120.75,110.5 r270 bottom
D31 "ON-PQFN4-8x8-2P-R-SP" ON-PQFN4-8x8-2P-R-SP 131.25,100 r0 top
D32 "TO-3-4E1S-R-SP" TO-3-4E1S-R-SP 142.85,110.5 r270 bottom
D33 "ON-PQFN4-8x8-2P-R-SP" ON-PQFN4-8x8-2P-R-SP 152.85,99.5 r180 top
D34 "TO-3-4E1S-R-SP" TO-3-4E1S-R-SP 152.1,110.5 r270 bottom
D35 "ON-PQFN4-8x8-2P-R-SP" ON-PQFN4-8x8-2P-R-SP 163.6,99.5 r180 top
D36 "TO-3-4E1S-R-SP" TO-3-4E1S-R-SP 161.35,110.5 r270 bottom
D37 "ON-PQFN4-8x8-2P-R-SP" ON-PQFN4-8x8-2P-R-SP 174.35,99.5 r180 top
D38 "TO-3-4E1S-R-SP" TO-3-4E1S-R-SP 212.75,81.4 r0 bottom
D39 "ON-PQFN4-8x8-2P-R-SP" ON-PQFN4-8x8-2P-R-SP 223.25,88.9 r90 top
D40 "TO-3-4E1S-R-SP" TO-3-4E1S-R-SP 212.75,90.65 r0 bottom
D41 "ON-PQFN4-8x8-2P-R-SP" ON-PQFN4-8x8-2P-R-SP 223.25,99.65 r90 top
D42 "TO-3-4E1S-R-SP" TO-3-4E1S-R-SP 212.75,99.9 r0 bottom
D43 "ON-PQFN4-8x8-2P-R-SP" ON-PQFN4-8x8-2P-R-SP 223.25,110.4 r90 top
D44 "TO-3-4E1S-R-SP" TO-3-4E1S-R-SP 213.5,124.5 r270 bottom
D45 "ON-PQFN4-8x8-2P-R-SP" ON-PQFN4-8x8-2P-R-SP 223.75,132 r270 top
D46 "TO-3-4E1S-R-SP" TO-3-4E1S-R-SP 212.75,131.25 r0 bottom
D47 "ON-PQFN4-8x8-2P-R-SP" ON-PQFN4-8x8-2P-R-SP 223.75,142.75 r270 top
D48 "TO-3-4E1S-R-SP" TO-3-4E1S-R-SP 212.75,140.5 r0 bottom
D49 "ON-PQFN4-8x8-2P-R-SP" ON-PQFN4-8x8-2P-R-SP 223.75,153.5 r270 top
D50 "TO-ESC-R-SP" TO-ESC-R-SP 75.75,159.25 r0 top
D51 "TO-ESC-R-SP" TO-ESC-R-SP 75.75,150 r0 top
D52 "TO-ESC-R-SP" TO-ESC-R-SP 75.75,140.75 r0 top
D53 "TO-ESC-R-SP" TO-ESC-R-SP 75.75,131.5 r0 top
D54 "TO-ESC-R-SP" TO-ESC-R-SP 75.75,118.65 r0 top
D55 "TO-ESC-R-SP" TO-ESC-R-SP 75.75,109.4 r0 top
D56 "TO-ESC-R-SP" TO-ESC-R-SP 75.75,100.15 r0 top
D57 "TO-ESC-R-SP" TO-ESC-R-SP 75.75,90.9 r0 top
D58 "TO-ESC-R-SP" TO-ESC-R-SP 104.75,115 r90 top
D59 "TO-ESC-R-SP" TO-ESC-R-SP 114,115 r90 top
D60 "TO-ESC-R-SP" TO-ESC-R-SP 123.25,115 r90 top
D61 "TO-ESC-R-SP" TO-ESC-R-SP 145.35,115 r90 top
D62 "TO-ESC-R-SP" TO-ESC-R-SP 132.5,115 r90 top
D63 "TO-ESC-R-SP" TO-ESC-R-SP 154.6,115 r90 top
D64 "TO-ESC-R-SP" TO-ESC-R-SP 163.85,115 r90 top
D65 "TO-ESC-R-SP" TO-ESC-R-SP 173.1,115 r90 top
D66 "TO-ESC-R-SP" TO-ESC-R-SP 208.25,83.9 r180 top
D67 "TO-ESC-R-SP" TO-ESC-R-SP 208.25,93.15 r180 top
D68 "TO-ESC-R-SP" TO-ESC-R-SP 208.25,102.4 r180 top
D69 "TO-ESC-R-SP" TO-ESC-R-SP 208.25,111.65 r180 top
D70 "TO-ESC-R-SP" TO-ESC-R-SP 208.25,124.5 r180 top
D71 "TO-ESC-R-SP" TO-ESC-R-SP 208.25,133.75 r180 top
D72 "TO-ESC-R-SP" TO-ESC-R-SP 208.25,143 r180 top
D73 "TO-ESC-R-SP" TO-ESC-R-SP 208.25,152.25 r180 top
DR1 "ONEPOINT-R-SP" ONEPOINT-R-SP#1 56.695,127.025 r270 top
DR2 "ONEPOINT-R-SP" ONEPOINT-R-SP#2 136.8,93.75 r270 top
DR3 "ONEPOINT-R-SP" ONEPOINT-R-SP#3 224.5,125.7 r0 top
DS1 "D-ROHM-1608-R-SP" D-ROHM-1608-R-SP 120.75,157.25 r270 top
DS2 "D-ROHM-1608-R-SP" D-ROHM-1608-R-SP 119.25,157.25 r270 top
DS3 "D-ROHM-1608-R-SP" D-ROHM-1608-R-SP 117.75,157.25 r270 top
DS4 "D-ROHM-1608-R-SP" D-ROHM-1608-R-SP 116.25,157.25 r270 top
FL1 "TDK-ACM4520-R-SP" TDK-ACM4520-R-SP 99.75,147.25 r270 top
IC1 "LT-20-Lead-Plastic-TSSOP-FE-R-SP-17p" LT-20-Lead-Plastic-TSSOP-FE-R-SP-17p 68,38.65 r270 top
IC2 "LT-TSSOP-16-FE-R-SP" LT-TSSOP-16-FE-R-SP 177.5,54.25 r90 top
IC3 "LT-TSOT-23-6-R-SP" LT-TSOT-23-6-R-SP 209.5,45 r90 bottom
IC4 "TO-SSOP5-P-0.95-R-SP" TO-SSOP5-P-0.95-R-SP 107.5,137.5 r180 top
IC5 "TO-SSOP5-P-0.95-R-SP" TO-SSOP5-P-0.95-R-SP 98,137.5 r180 top
IC6 "TO-TSSOP20B-R-SP" TO-TSSOP20B-R-SP 154.75,145.75 r270 top
IC7 "XI-VQFP100-R-SP" XI-VQFP100-R-SP 129,146.5 r90 top
IC8 "TO-TSSOP20B-R-SP" TO-TSSOP20B-R-SP 154.75,154.75 r270 top
IC9 "TI-DCK5-R-SP" TI-DCK5-R-SP 184.5,150 r90 top
IC10 "TI-D8-R-SP" TI-D8-R-SP 82.25,81.15 r270 top
IC11 "TI-D8-R-SP" TI-D8-R-SP 182.85,121.5 r0 top
IC12 "TI-D8-R-SP" TI-D8-R-SP 201.75,162 r90 top
IC13 "TO-SSOP8-P-0.50A-R-SP" TO-SSOP8-P-0.50A-R-SP 186.25,144.75 r90 top
IC14 "TO-SSOP8-P-0.50A-R-SP" TO-SSOP8-P-0.50A-R-SP 184.25,139.75 r90 top
IC15 "TO-SSOP8-P-0.50A-R-SP" TO-SSOP8-P-0.50A-R-SP 178.5,144.75 r90 top
IC16 "TO-SSOP8-P-0.50A-R-SP" TO-SSOP8-P-0.50A-R-SP 170.75,139.75 r90 top
IC17 "TO-SSOP8-P-0.50A-R-SP" TO-SSOP8-P-0.50A-R-SP 177.5,139.75 r90 top
IC18 "TO-SSOP8-P-0.50A-R-SP" TO-SSOP8-P-0.50A-R-SP 170.75,144.75 r90 top
IC19 "TI-DCK5-R-SP" TI-DCK5-R-SP 180,150 r90 top
IC20 "TI-DCK5-R-SP" TI-DCK5-R-SP 175.5,150 r90 top
IC21 "TI-DCK5-R-SP" TI-DCK5-R-SP 171,150 r90 top
IC22 "ABRACON-ASE-3.2x2.5-R-SP" ABRACON-ASE-3.2x2.5-R-SP 143.75,150 r90 top
PC1 "TO-11-4L1S-R-SP" TO-11-4L1S-R-SP 82.25,157.75 r90 bottom
PC2 "TO-11-4L1S-R-SP" TO-11-4L1S-R-SP 82.25,148.5 r90 bottom
PC3 "TO-11-4L1S-R-SP" TO-11-4L1S-R-SP 82.25,139.25 r90 bottom
PC4 "TO-11-4L1S-R-SP" TO-11-4L1S-R-SP 82.25,130 r90 bottom
PC5 "TO-11-4L1S-R-SP" TO-11-4L1S-R-SP 82.25,117.15 r90 bottom
PC6 "TO-11-4L1S-R-SP" TO-11-4L1S-R-SP 82.25,107.9 r90 bottom
PC7 "TO-11-4L1S-R-SP" TO-11-4L1S-R-SP 82.25,98.65 r90 bottom
PC8 "TO-11-4L1S-R-SP" TO-11-4L1S-R-SP 82.25,89.4 r90 bottom
PC9 "TO-11-4L1S-R-SP" TO-11-4L1S-R-SP 106.25,121.5 r180 bottom
PC10 "TO-11-4L1S-R-SP" TO-11-4L1S-R-SP 115.5,121.5 r180 bottom
PC11 "TO-11-4L1S-R-SP" TO-11-4L1S-R-SP 124.75,121.5 r180 bottom
PC12 "TO-11-4L1S-R-SP" TO-11-4L1S-R-SP 134,121.5 r180 bottom
PC13 "TO-11-4L1S-R-SP" TO-11-4L1S-R-SP 146.85,121.5 r180 bottom
PC14 "TO-11-4L1S-R-SP" TO-11-4L1S-R-SP 156.1,121.5 r180 bottom
PC15 "TO-11-4L1S-R-SP" TO-11-4L1S-R-SP 165.35,121.5 r180 bottom
PC16 "TO-11-4L1S-R-SP" TO-11-4L1S-R-SP 174.6,121.5 r180 bottom
PC17 "TO-11-4L1S-R-SP" TO-11-4L1S-R-SP 201.75,85.4 r270 bottom
PC18 "TO-11-4L1S-R-SP" TO-11-4L1S-R-SP 201.75,94.65 r270 bottom
PC19 "TO-11-4L1S-R-SP" TO-11-4L1S-R-SP 201.75,103.9 r270 bottom
PC20 "TO-11-4L1S-R-SP" TO-11-4L1S-R-SP 201.75,113.15 r270 bottom
PC21 "TO-11-4L1S-R-SP" TO-11-4L1S-R-SP 201.75,126 r270 bottom
PC22 "TO-11-4L1S-R-SP" TO-11-4L1S-R-SP 201.75,135.25 r270 bottom
PC23 "TO-11-4L1S-R-SP" TO-11-4L1S-R-SP 201.75,144.5 r270 bottom
PC24 "TO-11-4L1S-R-SP" TO-11-4L1S-R-SP 201.75,153.75 r270 bottom
Q1 "TO-2-8T1A-R-SP" TO-2-8T1A-R-SP 75.05,51.35 r0 top
Q2 "TO-2-3X1S-R-SP" TO-2-3X1S-R-SP 207.5,37.25 r180 bottom
Q3 "TO-2-5W1A-R-SP" TO-2-5W1A-R-SP 70.25,157.25 r0 top
Q4 "TO-2-2H1B-GSD-123-R-SP" TO-2-2H1B-GSD-123-R-SP 88,156.35 r0 bottom
Q5 "TO-2-5W1A-R-SP" TO-2-5W1A-R-SP 70.25,148 r0 top
Q6 "TO-2-2H1B-GSD-123-R-SP" TO-2-2H1B-GSD-123-R-SP 88,147.1 r0 bottom
Q7 "TO-2-5W1A-R-SP" TO-2-5W1A-R-SP 70.25,138.75 r0 top
Q8 "TO-2-2H1B-GSD-123-R-SP" TO-2-2H1B-GSD-123-R-SP 88,137.85 r0 bottom
Q9 "TO-2-5W1A-R-SP" TO-2-5W1A-R-SP 70.25,129.5 r0 top
Q10 "TO-2-2H1B-GSD-123-R-SP" TO-2-2H1B-GSD-123-R-SP 88,128.6 r0 bottom
Q11 "TO-2-5W1A-R-SP" TO-2-5W1A-R-SP 70.25,116.65 r0 top
Q12 "TO-2-2H1B-GSD-123-R-SP" TO-2-2H1B-GSD-123-R-SP 87.85,115.7 r0 bottom
Q13 "TO-2-5W1A-R-SP" TO-2-5W1A-R-SP 70.25,107.4 r0 top
Q14 "TO-2-2H1B-GSD-123-R-SP" TO-2-2H1B-GSD-123-R-SP 87.85,106.45 r0 bottom
Q15 "TO-2-5W1A-R-SP" TO-2-5W1A-R-SP 70.25,98.15 r0 top
Q16 "TO-2-2H1B-GSD-123-R-SP" TO-2-2H1B-GSD-123-R-SP 87.85,97.2 r0 bottom
Q17 "TO-2-5W1A-R-SP" TO-2-5W1A-R-SP 70.25,88.9 r0 top
Q18 "TO-2-2H1B-GSD-123-R-SP" TO-2-2H1B-GSD-123-R-SP 87.85,87.95 r0 bottom
Q19 "TO-2-5W1A-R-SP" TO-2-5W1A-R-SP 106.75,109.5 r90 top
Q20 "TO-2-2H1B-GSD-123-R-SP" TO-2-2H1B-GSD-123-R-SP 107.65,127.25 r90 bottom
Q21 "TO-2-5W1A-R-SP" TO-2-5W1A-R-SP 116,109.5 r90 top
Q22 "TO-2-2H1B-GSD-123-R-SP" TO-2-2H1B-GSD-123-R-SP 116.9,127.25 r90 bottom
Q23 "TO-2-5W1A-R-SP" TO-2-5W1A-R-SP 125.25,109.5 r90 top
Q24 "TO-2-2H1B-GSD-123-R-SP" TO-2-2H1B-GSD-123-R-SP 126.15,127.25 r90 bottom
Q25 "TO-2-5W1A-R-SP" TO-2-5W1A-R-SP 134.5,109.5 r90 top
Q26 "TO-2-2H1B-GSD-123-R-SP" TO-2-2H1B-GSD-123-R-SP 135.4,127.25 r90 bottom
Q27 "TO-2-5W1A-R-SP" TO-2-5W1A-R-SP 147.35,109.5 r90 top
Q28 "TO-2-2H1B-GSD-123-R-SP" TO-2-2H1B-GSD-123-R-SP 147.4,128.9 r270 bottom
Q29 "TO-2-5W1A-R-SP" TO-2-5W1A-R-SP 156.6,109.5 r90 top
Q30 "TO-2-2H1B-GSD-123-R-SP" TO-2-2H1B-GSD-123-R-SP 156.65,128.9 r270 bottom
Q31 "TO-2-5W1A-R-SP" TO-2-5W1A-R-SP 165.85,109.5 r90 top
Q32 "TO-2-2H1B-GSD-123-R-SP" TO-2-2H1B-GSD-123-R-SP 165.9,128.9 r270 bottom
Q33 "TO-2-5W1A-R-SP" TO-2-5W1A-R-SP 175.1,109.5 r90 top
Q34 "TO-2-2H1B-GSD-123-R-SP" TO-2-2H1B-GSD-123-R-SP 175.15,128.9 r270 bottom
Q35 "TO-2-5W1A-R-SP" TO-2-5W1A-R-SP 213.75,85.9 r180 top
Q36 "TO-2-2H1B-GSD-123-R-SP" TO-2-2H1B-GSD-123-R-SP 196.7,88.35 r90 bottom
Q37 "TO-2-5W1A-R-SP" TO-2-5W1A-R-SP 213.75,95.15 r180 top
Q38 "TO-2-2H1B-GSD-123-R-SP" TO-2-2H1B-GSD-123-R-SP 196.7,97.6 r90 bottom
Q39 "TO-2-5W1A-R-SP" TO-2-5W1A-R-SP 213.75,104.4 r180 top
Q40 "TO-2-2H1B-GSD-123-R-SP" TO-2-2H1B-GSD-123-R-SP 196.7,106.85 r90 bottom
Q41 "TO-2-5W1A-R-SP" TO-2-5W1A-R-SP 213.75,113.65 r180 top
Q42 "TO-2-2H1B-GSD-123-R-SP" TO-2-2H1B-GSD-123-R-SP 196.7,116.1 r90 bottom
Q43 "TO-2-5W1A-R-SP" TO-2-5W1A-R-SP 213.75,126.5 r180 top
Q44 "TO-2-2H1B-GSD-123-R-SP" TO-2-2H1B-GSD-123-R-SP 196,127.4 r180 bottom
Q45 "TO-2-5W1A-R-SP" TO-2-5W1A-R-SP 213.75,135.75 r180 top
Q46 "TO-2-2H1B-GSD-123-R-SP" TO-2-2H1B-GSD-123-R-SP 196,136.65 r180 bottom
Q47 "TO-2-5W1A-R-SP" TO-2-5W1A-R-SP 213.75,145 r180 top
Q48 "TO-2-2H1B-GSD-123-R-SP" TO-2-2H1B-GSD-123-R-SP 196,145.9 r180 bottom
Q49 "TO-2-5W1A-R-SP" TO-2-5W1A-R-SP 213.75,154.25 r180 top
Q50 "TO-2-2H1B-GSD-123-R-SP" TO-2-2H1B-GSD-123-R-SP 196,155.15 r180 bottom
R1 "R3216-R-SP" R3216-R-SP#1 62.5,52.5 r180 bottom
R2 "R1608_R_SP" R1608_R_SP#1 64.1,31.35 r0 top
R3 "R3216-R-SP" R3216-R-SP#1 66.5,51 r90 bottom
R4 "R1608_R_SP" R1608_R_SP#1 65.5,33.25 r180 top
R5 "R3216-R-SP" R3216-R-SP#1 45.5,45 r90 bottom
R6 "R1608_R_SP" R1608_R_SP#1 71.5,31.75 r0 top
R7 "R3216-R-SP" R3216-R-SP#1 66.5,46 r90 bottom
R8 "R2125_R_SP" R2125_R_SP 133,37.5 r90 bottom
R9 "R3216-R-SP" R3216-R-SP#1 45.5,40 r90 bottom
R10 "R3216-R-SP" R3216-R-SP#1 45.5,35 r90 bottom
R11 "R1608_R_SP" R1608_R_SP#2 69.5,38.75 r270 bottom
R12 "R1608_R_SP" R1608_R_SP#1 71.5,33.25 r180 top
R13 "R1608_R_SP" R1608_R_SP#1 74.5,31.75 r0 top
R14 "R1608_R_SP" R1608_R_SP#1 74.5,34.75 r0 top
R15 "R1608_R_SP" R1608_R_SP#2 45.5,30.5 r90 bottom
R16 "R1608_R_SP" R1608_R_SP#1 74.5,36.25 r180 top
R17 "R1608_R_SP" R1608_R_SP#1 72,45 r90 top
R18 "R1608_R_SP" R1608_R_SP#1 74.85,40.95 r90 top
R19 "R3216-R-SP" R3216-R-SP#2 76.7,40.3 r270 top
R20 "R2125_R_SP" R2125_R_SP 188.75,50.75 r180 bottom
R21 "R2125_R_SP" R2125_R_SP 188.75,56 r180 bottom
R22 "R1005_R_SP" R1005_R_SP#1 172.25,54.25 r0 top
R23 "R2125_R_SP" R2125_R_SP 188.75,52.5 r180 bottom
R24 "R1005_R_SP" R1005_R_SP#1 184.7,54 r90 top
R25 "R2125_R_SP" R2125_R_SP 188.75,54.25 r180 bottom
R26 "R1005_R_SP" R1005_R_SP#1 182.35,52.5 r0 top
R27 "R1005_R_SP" R1005_R_SP#1 183.7,54 r90 top
R28 "R1608_R_SP" R1608_R_SP#2 215.05,41 r0 bottom
R29 "R1608_R_SP" R1608_R_SP#2 213.35,42.5 r0 bottom
R30 "R1608_R_SP" R1608_R_SP#2 206.9,41.4 r90 bottom
R31 "R1608_R_SP" R1608_R_SP#2 218.25,40.25 r180 bottom
R32 "R1608_R_SP" R1608_R_SP#2 214.75,47.25 r180 bottom
R33 "R-WSL0603-R-SP" R-WSL0603-R-SP 209,40 r180 bottom
R34 "R1608_R_SP" R1608_R_SP#2 213.35,44.05 r180 bottom
R36 "R1608_R_SP" R1608_R_SP#1 106.25,140.25 r180 top
R39 "R1608_R_SP" R1608_R_SP#1 96.75,140.25 r180 top
R40 "R1005_R_SP" R1005_R_SP#1 161,148.75 r180 top
R41 "R1005_R_SP" R1005_R_SP#1 161,147.75 r180 top
R42 "R1005_R_SP" R1005_R_SP#1 161,146.75 r180 top
R43 "R1005_R_SP" R1005_R_SP#1 161,145.75 r180 top
R44 "R1005_R_SP" R1005_R_SP#1 161,144.75 r180 top
R45 "R1005_R_SP" R1005_R_SP#1 161,143.75 r180 top
R46 "R1005_R_SP" R1005_R_SP#1 161,142.75 r180 top
R47 "R1005_R_SP" R1005_R_SP#1 161,141.75 r180 top
R48 "R1005_R_SP" R1005_R_SP#1 148.5,149.25 r0 top
R49 "R1005_R_SP" R1005_R_SP#1 148.5,148.25 r0 top
R50 "R1005_R_SP" R1005_R_SP#1 148.5,147.25 r0 top
R51 "R1005_R_SP" R1005_R_SP#1 148.5,146.25 r0 top
R52 "R1005_R_SP" R1005_R_SP#1 148.5,145.25 r0 top
R53 "R1005_R_SP" R1005_R_SP#1 148.5,144.25 r0 top
R54 "R1005_R_SP" R1005_R_SP#1 148.5,143.25 r0 top
R55 "R1005_R_SP" R1005_R_SP#1 148.5,142.25 r0 top
R56 "R1005_R_SP" R1005_R_SP#1 179.35,162.2 r270 top
R57 "R1005_R_SP" R1005_R_SP#1 174.3,162.2 r270 top
R58 "R1005_R_SP" R1005_R_SP#1 161,157.75 r180 top
R59 "R1005_R_SP" R1005_R_SP#1 161,156.75 r180 top
R60 "R1005_R_SP" R1005_R_SP#1 161,155.75 r180 top
R61 "R1005_R_SP" R1005_R_SP#1 161,154.75 r180 top
R62 "R1005_R_SP" R1005_R_SP#1 161,153.75 r180 top
R63 "R1005_R_SP" R1005_R_SP#1 161,152.75 r180 top
R64 "R1005_R_SP" R1005_R_SP#1 161,151.75 r180 top
R65 "R1005_R_SP" R1005_R_SP#1 161,150.75 r180 top
R66 "R1005_R_SP" R1005_R_SP#1 148.5,158.25 r0 top
R67 "R1005_R_SP" R1005_R_SP#1 148.5,157.25 r0 top
R68 "R1005_R_SP" R1005_R_SP#1 148.5,156.25 r0 top
R69 "R1005_R_SP" R1005_R_SP#1 148.5,155.25 r0 top
R70 "R1005_R_SP" R1005_R_SP#1 148.5,154.25 r0 top
R71 "R1005_R_SP" R1005_R_SP#1 148.5,153.25 r0 top
R72 "R1005_R_SP" R1005_R_SP#1 148.5,152.25 r0 top
R73 "R1005_R_SP" R1005_R_SP#1 148.5,151.25 r0 top
R74 "R1005_R_SP" R1005_R_SP#1 141,150 r0 top
R75 "R1005_R_SP" R1005_R_SP#1 127.5,161.25 r270 top
R76 "R1005_R_SP" R1005_R_SP#1 129.5,161.25 r270 top
R77 "R1005_R_SP" R1005_R_SP#1 125.5,161.25 r270 top
R78 "R1005_R_SP" R1005_R_SP#1 123.5,161.25 r270 top
R79 "R1005_R_SP" R1005_R_SP#1 141,151 r180 top
R80 "R1608_R_SP" R1608_R_SP#2 74,160.25 r0 bottom
R81 "R1005_R_SP" R1005_R_SP#2 88.5,159.95 r0 bottom
R82 "R1608_R_SP" R1608_R_SP#2 75,151.75 r270 bottom
R83 "R1005_R_SP" R1005_R_SP#2 88.5,150.7 r0 bottom
R84 "R1608_R_SP" R1608_R_SP#2 75,142.5 r270 bottom
R85 "R1005_R_SP" R1005_R_SP#2 88.5,141.45 r0 bottom
R86 "R1608_R_SP" R1608_R_SP#2 75,133.25 r270 bottom
R87 "R1005_R_SP" R1005_R_SP#2 88.5,132.2 r0 bottom
R88 "R1608_R_SP" R1608_R_SP#2 75,120.4 r270 bottom
R89 "R1005_R_SP" R1005_R_SP#2 87.45,119.3 r180 bottom
R90 "R1608_R_SP" R1608_R_SP#2 75,111.15 r270 bottom
R91 "R1005_R_SP" R1005_R_SP#2 87.45,110.05 r180 bottom
R92 "R1608_R_SP" R1608_R_SP#2 75,101.9 r270 bottom
R93 "R1005_R_SP" R1005_R_SP#2 87.45,100.8 r180 bottom
R94 "R1608_R_SP" R1608_R_SP#2 75,92.65 r270 bottom
R95 "R1005_R_SP" R1005_R_SP#2 87.45,91.55 r180 bottom
R96 "R1608_R_SP" R1608_R_SP#2 103.75,113.25 r90 bottom
R97 "R1005_R_SP" R1005_R_SP#2 104.05,127.75 r90 bottom
R98 "R1608_R_SP" R1608_R_SP#2 112.25,114.25 r0 bottom
R99 "R1005_R_SP" R1005_R_SP#2 113.3,127.75 r90 bottom
R100 "R1005_R_SP" R1005_R_SP#2 122.55,127.75 r90 bottom
R101 "R1608_R_SP" R1608_R_SP#2 121.5,114.25 r0 bottom
R102 "R1005_R_SP" R1005_R_SP#2 131.8,127.75 r90 bottom
R103 "R1608_R_SP" R1608_R_SP#2 130.75,114.25 r0 bottom
R104 "R1608_R_SP" R1608_R_SP#2 143.6,114.25 r0 bottom
R105 "R1005_R_SP" R1005_R_SP#2 145.75,127.25 r180 bottom
R106 "R1608_R_SP" R1608_R_SP#2 152.85,114.25 r0 bottom
R107 "R1005_R_SP" R1005_R_SP#2 155,127.25 r180 bottom
R108 "R1608_R_SP" R1608_R_SP#2 162.1,114.25 r0 bottom
R109 "R1005_R_SP" R1005_R_SP#2 164.25,127.25 r180 bottom
R110 "R1608_R_SP" R1608_R_SP#2 171.35,114.25 r0 bottom
R111 "R1005_R_SP" R1005_R_SP#2 173.5,127.25 r180 bottom
R112 "R1608_R_SP" R1608_R_SP#2 209,82.15 r90 bottom
R113 "R1005_R_SP" R1005_R_SP#2 196,84.5 r270 bottom
R114 "R1608_R_SP" R1608_R_SP#2 209,91.4 r90 bottom
R115 "R1005_R_SP" R1005_R_SP#2 196,93.75 r270 bottom
R116 "R1608_R_SP" R1608_R_SP#2 209,100.65 r90 bottom
R117 "R1005_R_SP" R1005_R_SP#2 196,103 r270 bottom
R118 "R1608_R_SP" R1608_R_SP#2 209,109.9 r90 bottom
R119 "R1005_R_SP" R1005_R_SP#2 196,112.25 r270 bottom
R120 "R1608_R_SP" R1608_R_SP#2 211,126 r270 bottom
R121 "R1005_R_SP" R1005_R_SP#2 195.5,123.8 r180 bottom
R122 "R1608_R_SP" R1608_R_SP#2 209,132 r90 bottom
R123 "R1005_R_SP" R1005_R_SP#2 195.5,133.05 r180 bottom
R124 "R1608_R_SP" R1608_R_SP#2 209,141.25 r90 bottom
R125 "R1005_R_SP" R1005_R_SP#2 195.5,142.3 r180 bottom
R126 "R1608_R_SP" R1608_R_SP#2 209,150.5 r90 bottom
R127 "R1005_R_SP" R1005_R_SP#2 195.5,151.55 r180 bottom
R128 "R1608_R_SP" R1608_R_SP#1 166,136.75 r90 top
R129 "R1608_R_SP" R1608_R_SP#1 164.5,136.75 r90 top
R130 "R1608_R_SP" R1608_R_SP#1 166,139.75 r90 top
R131 "R1608_R_SP" R1608_R_SP#1 164.5,140.75 r90 top
R132 "R1608_R_SP" R1608_R_SP#1 166,142.75 r90 top
R133 "R1608_R_SP" R1608_R_SP#1 164.5,143.75 r90 top
R134 "R1608_R_SP" R1608_R_SP#1 166,146.75 r90 top
R135 "R1608_R_SP" R1608_R_SP#1 164.5,146.75 r90 top
R136 "R1005_R_SP" R1005_R_SP#1 181.75,153 r0 top
R137 "R1005_R_SP" R1005_R_SP#1 179.85,153 r0 top
R138 "R1005_R_SP" R1005_R_SP#1 182.25,150.5 r90 top
R139 "R1005_R_SP" R1005_R_SP#1 177.25,153 r0 top
R140 "R1005_R_SP" R1005_R_SP#1 175.35,153 r0 top
R141 "R1005_R_SP" R1005_R_SP#1 177.75,150.5 r90 top
R142 "R1005_R_SP" R1005_R_SP#1 172.75,153 r0 top
R143 "R1005_R_SP" R1005_R_SP#1 170.85,153 r0 top
R144 "R1005_R_SP" R1005_R_SP#1 173.25,150.5 r90 top
R145 "R1005_R_SP" R1005_R_SP#1 120.75,159.75 r270 top
R146 "R1005_R_SP" R1005_R_SP#1 119.25,159.75 r270 top
R147 "R1005_R_SP" R1005_R_SP#1 117.75,159.75 r270 top
R148 "R1005_R_SP" R1005_R_SP#1 116.25,159.75 r270 top
R149 "R1005_R_SP" R1005_R_SP#1 109.1,146.15 r90 top
R150 "R1005_R_SP" R1005_R_SP#1 110.35,146.15 r90 top
R151 "R1005_R_SP" R1005_R_SP#1 111.65,146.15 r90 top
R152 "R1005_R_SP" R1005_R_SP#1 112.9,146.15 r90 top
R153 "R1005_R_SP" R1005_R_SP#1 147.2,135 r270 top
R154 "R1608_R_SP" R1608_R_SP#2 211.75,39.5 r90 bottom
R155 "R2125_R_SP" R2125_R_SP 203.5,45 r180 bottom
R156 "R1005_R_SP" R1005_R_SP#1 189.55,162.2 r270 top
R157 "R1005_R_SP" R1005_R_SP#1 185.75,162.2 r270 top
R158 "R1005_R_SP" R1005_R_SP#1 184.45,162.2 r270 top
R159 "R1005_R_SP" R1005_R_SP#1 183.2,162.2 r270 top
R160 "R1005_R_SP" R1005_R_SP#2 189.55,166.95 r270 bottom
R161 "R1005_R_SP" R1005_R_SP#2 188.25,166.95 r270 bottom
R162 "R1005_R_SP" R1005_R_SP#2 185.75,166.95 r270 bottom
R163 "R1005_R_SP" R1005_R_SP#2 184.45,166.95 r270 bottom
R164 "R1005_R_SP" R1005_R_SP#2 183.2,166.95 r270 bottom
R165 "R1005_R_SP" R1005_R_SP#2 179.4,166.95 r270 bottom
R166 "R1005_R_SP" R1005_R_SP#2 178.1,166.95 r270 bottom
R167 "R1005_R_SP" R1005_R_SP#2 176.85,166.95 r270 bottom
R168 "R1608_R_SP" R1608_R_SP#1 107,115.75 r0 top
R169 "R1608_R_SP" R1608_R_SP#1 116.25,115.75 r0 top
R170 "R1608_R_SP" R1608_R_SP#1 125.5,115.75 r0 top
R171 "R1608_R_SP" R1608_R_SP#1 134.75,115.75 r0 top
R172 "R1608_R_SP" R1608_R_SP#1 147.6,115.75 r0 top
R173 "R1608_R_SP" R1608_R_SP#1 156.85,115.75 r0 top
R174 "R1608_R_SP" R1608_R_SP#1 166.1,115.75 r0 top
R175 "R1608_R_SP" R1608_R_SP#1 175.35,115.75 r0 top
R176 "R1608_R_SP" R1608_R_SP#1 76.5,157 r270 top
R177 "R1608_R_SP" R1608_R_SP#1 76.5,147.75 r270 top
R178 "R1608_R_SP" R1608_R_SP#1 76.5,138.5 r270 top
R179 "R1608_R_SP" R1608_R_SP#1 76.5,129.25 r270 top
R180 "R1608_R_SP" R1608_R_SP#1 76.5,116.4 r270 top
R181 "R1608_R_SP" R1608_R_SP#1 76.5,107.15 r270 top
R182 "R1608_R_SP" R1608_R_SP#1 76.5,97.9 r270 top
R183 "R1608_R_SP" R1608_R_SP#1 76.5,88.65 r270 top
R184 "R1608_R_SP" R1608_R_SP#1 207.5,86.15 r90 top
R185 "R1608_R_SP" R1608_R_SP#1 207.5,95.4 r90 top
R186 "R1608_R_SP" R1608_R_SP#1 207.5,104.65 r90 top
R187 "R1608_R_SP" R1608_R_SP#1 207.5,113.9 r90 top
R188 "R1608_R_SP" R1608_R_SP#1 207.5,126.75 r90 top
R189 "R1608_R_SP" R1608_R_SP#1 207.5,136 r90 top
R190 "R1608_R_SP" R1608_R_SP#1 207.5,145.25 r90 top
R191 "R1608_R_SP" R1608_R_SP#1 207.5,154.5 r90 top
R192 "R1005_R_SP" R1005_R_SP#1 184,152 r0 top
R193 "R3216-R-SP" R3216-R-SP#1 37,151.5 r180 bottom
R194 "R3216-R-SP" R3216-R-SP#1 30.25,143.5 r180 bottom
R195 "R3216-R-SP" R3216-R-SP#1 30.25,126.5 r180 bottom
R196 "R3216-R-SP" R3216-R-SP#1 30.25,109.5 r180 bottom
R197 "R1608_R_SP" R1608_R_SP#2 212.25,32 r180 bottom
R198 "R1005_R_SP" R1005_R_SP#1 188.3,162.2 r270 top
R199 "R3216-R-SP" R3216-R-SP#1 108.75,78 r180 bottom
R200 "R3216-R-SP" R3216-R-SP#1 125.75,78 r180 bottom
R201 "R3216-R-SP" R3216-R-SP#1 157.75,78 r180 bottom
R202 "R3216-R-SP" R3216-R-SP#1 174.5,75 r180 bottom
R203 "R3216-R-SP" R3216-R-SP#1 245.75,86 r270 bottom
R204 "R3216-R-SP" R3216-R-SP#1 245.75,108 r270 bottom
R205 "R3216-R-SP" R3216-R-SP#1 245.75,125 r270 bottom
R206 "R3216-R-SP" R3216-R-SP#1 245.75,147 r270 bottom
R207 "R1608_R_SP" R1608_R_SP#1 70.5,45 r270 top
R208 "R1608_R_SP" R1608_R_SP#2 210.25,37.75 r90 bottom
R209 "R1005_R_SP" R1005_R_SP#1 145.7,134.5 r180 top
R210 "R1005_R_SP" R1005_R_SP#1 115.6,151.5 r0 top
R211 "R1005_R_SP" R1005_R_SP#1 115.6,150.45 r0 top
R212 "R1005_R_SP" R1005_R_SP#1 115.6,149.45 r0 top
R213 "R1005_R_SP" R1005_R_SP#1 115.6,148.45 r0 top
R214 "R1005_R_SP" R1005_R_SP#1 75,154.5 r270 top
R215 "R1005_R_SP" R1005_R_SP#1 75,145.25 r270 top
R216 "R1005_R_SP" R1005_R_SP#1 75,136 r270 top
R217 "R1005_R_SP" R1005_R_SP#1 75,126.75 r270 top
R218 "R1005_R_SP" R1005_R_SP#1 75,113.9 r270 top
R219 "R1005_R_SP" R1005_R_SP#1 75,104.65 r270 top
R220 "R1005_R_SP" R1005_R_SP#1 75,95.4 r270 top
R221 "R1005_R_SP" R1005_R_SP#1 75,86.15 r270 top
R222 "R1005_R_SP" R1005_R_SP#1 109.5,114.25 r0 top
R223 "R1005_R_SP" R1005_R_SP#1 118.75,114.25 r0 top
R224 "R1005_R_SP" R1005_R_SP#1 128,114.25 r0 top
R225 "R1005_R_SP" R1005_R_SP#1 137.25,114.25 r0 top
R226 "R1005_R_SP" R1005_R_SP#1 150.1,114.25 r0 top
R227 "R1005_R_SP" R1005_R_SP#1 159.35,114.25 r0 top
R228 "R1005_R_SP" R1005_R_SP#1 168.6,114.25 r0 top
R229 "R1005_R_SP" R1005_R_SP#1 177.85,114.25 r0 top
R230 "R1005_R_SP" R1005_R_SP#1 209,88.65 r90 top
R231 "R1005_R_SP" R1005_R_SP#1 209,97.9 r90 top
R232 "R1005_R_SP" R1005_R_SP#1 209,107.15 r90 top
R233 "R1005_R_SP" R1005_R_SP#1 209,116.4 r90 top
R234 "R1005_R_SP" R1005_R_SP#1 209,129.25 r90 top
R235 "R1005_R_SP" R1005_R_SP#1 209,138.5 r90 top
R236 "R1005_R_SP" R1005_R_SP#1 209,147.75 r90 top
R237 "R1005_R_SP" R1005_R_SP#1 209,157 r90 top
R238 "R1005_R_SP" R1005_R_SP#1 187,162.2 r270 top
R239 "R1005_R_SP" R1005_R_SP#1 178.1,162.2 r270 top
R240 "R1005_R_SP" R1005_R_SP#1 176.85,162.2 r270 top
R241 "R1005_R_SP" R1005_R_SP#2 155,148 r180 bottom
R242 "R1005_R_SP" R1005_R_SP#2 155,147 r180 bottom
R243 "R1005_R_SP" R1005_R_SP#2 155,157 r180 bottom
R244 "R1005_R_SP" R1005_R_SP#2 155,156 r180 bottom
R245 "R1608_R_SP" R1608_R_SP#1 75,157 r270 top
R246 "R1608_R_SP" R1608_R_SP#1 75,147.75 r270 top
R247 "R1608_R_SP" R1608_R_SP#1 75,138.5 r270 top
R249 "R1608_R_SP" R1608_R_SP#1 75,129.25 r270 top
R251 "R1608_R_SP" R1608_R_SP#1 75,116.4 r270 top
R253 "R1608_R_SP" R1608_R_SP#1 75,107.15 r270 top
R255 "R1608_R_SP" R1608_R_SP#1 75,97.9 r270 top
R257 "R1608_R_SP" R1608_R_SP#1 75,88.65 r270 top
R258 "R1608_R_SP" R1608_R_SP#1 107,114.25 r0 top
R260 "R1608_R_SP" R1608_R_SP#1 116.25,114.25 r0 top
R262 "R1608_R_SP" R1608_R_SP#1 125.5,114.25 r0 top
R264 "R1608_R_SP" R1608_R_SP#1 147.6,114.25 r0 top
R266 "R1608_R_SP" R1608_R_SP#1 134.75,114.25 r0 top
R268 "R1608_R_SP" R1608_R_SP#1 156.85,114.25 r0 top
R270 "R1608_R_SP" R1608_R_SP#1 166.1,114.25 r0 top
R272 "R1608_R_SP" R1608_R_SP#1 175.35,114.25 r0 top
R274 "R1608_R_SP" R1608_R_SP#1 209,86.15 r90 top
R276 "R1608_R_SP" R1608_R_SP#1 209,95.4 r90 top
R278 "R1608_R_SP" R1608_R_SP#1 209,104.65 r90 top
R280 "R1608_R_SP" R1608_R_SP#1 209,113.9 r90 top
R282 "R1608_R_SP" R1608_R_SP#1 209,126.75 r90 top
R284 "R1608_R_SP" R1608_R_SP#1 209,136 r90 top
R286 "R1608_R_SP" R1608_R_SP#1 209,145.25 r90 top
R288 "R1608_R_SP" R1608_R_SP#1 209,154.5 r90 top
R289 "R1005_R_SP" R1005_R_SP#1 88.25,80 r270 top
R290 "R1005_R_SP" R1005_R_SP#1 87.25,80 r270 top
R291 "R1005_R_SP" R1005_R_SP#1 184,127.5 r0 top
R292 "R1005_R_SP" R1005_R_SP#1 184,126.5 r180 top
R293 "R1005_R_SP" R1005_R_SP#1 195.75,163.15 r90 top
R294 "R1005_R_SP" R1005_R_SP#1 196.75,163.15 r270 top
R295 "R1005_R_SP" R1005_R_SP#1 173.1,52.1 r90 top
R296 "R1005_R_SP" R1005_R_SP#1 182.7,54 r90 top
R297 "R1005_R_SP" R1005_R_SP#2 182.7,54.45 r270 bottom
R298 "R1608_R_SP" R1608_R_SP#1 82.25,167 r180 top
R299 "R1608_R_SP" R1608_R_SP#1 82.25,164.5 r180 top
R300 "R1608_R_SP" R1608_R_SP#2 218.25,41.75 r180 bottom
R301 "R1608_R_SP" R1608_R_SP#2 198.25,64.5 r270 bottom
R302 "R1608_R_SP" R1608_R_SP#2 196.75,64.5 r270 bottom
R303 "R1608_R_SP" R1608_R_SP#2 219.25,65.5 r270 bottom
R304 "R1608_R_SP" R1608_R_SP#2 217.75,65.5 r270 bottom
R305 "R1608_R_SP" R1608_R_SP#2 234.25,65.5 r270 bottom
R306 "R1608_R_SP" R1608_R_SP#2 232.75,65.5 r270 bottom
R307 "R1608_R_SP" R1608_R_SP#2 244.75,35.5 r90 bottom
R308 "R1608_R_SP" R1608_R_SP#2 246.25,35.5 r90 bottom
R309 "R1005_R_SP" R1005_R_SP#1 189.65,144.95 r90 top
R310 "R1005_R_SP" R1005_R_SP#1 181.9,144.95 r90 top
R311 "R1005_R_SP" R1005_R_SP#1 174.15,144.95 r90 top
R312 "R1005_R_SP" R1005_R_SP#1 61.3,31.65 r180 top
R313 "R1005_R_SP" R1005_R_SP#2 88,154.65 r0 bottom
R314 "R1005_R_SP" R1005_R_SP#2 88,145.4 r0 bottom
R315 "R1005_R_SP" R1005_R_SP#2 88,136.15 r0 bottom
R316 "R1005_R_SP" R1005_R_SP#2 88,126.9 r0 bottom
R317 "R1005_R_SP" R1005_R_SP#2 87.85,114 r0 bottom
R318 "R1005_R_SP" R1005_R_SP#2 87.85,104.75 r0 bottom
R319 "R1005_R_SP" R1005_R_SP#2 87.85,95.5 r0 bottom
R320 "R1005_R_SP" R1005_R_SP#2 87.85,86.25 r0 bottom
R321 "R1005_R_SP" R1005_R_SP#2 109.35,127.25 r90 bottom
R322 "R1005_R_SP" R1005_R_SP#2 118.6,127.25 r90 bottom
R323 "R1005_R_SP" R1005_R_SP#2 127.85,127.25 r90 bottom
R324 "R1005_R_SP" R1005_R_SP#2 137.1,127.25 r90 bottom
R325 "R1005_R_SP" R1005_R_SP#2 145.7,128.9 r270 bottom
R326 "R1005_R_SP" R1005_R_SP#2 154.95,128.9 r270 bottom
R327 "R1005_R_SP" R1005_R_SP#2 164.2,128.9 r270 bottom
R328 "R1005_R_SP" R1005_R_SP#2 173.45,128.9 r270 bottom
R329 "R1005_R_SP" R1005_R_SP#2 198.4,88.35 r90 bottom
R330 "R1005_R_SP" R1005_R_SP#2 198.4,97.6 r90 bottom
R331 "R1005_R_SP" R1005_R_SP#2 198.4,106.85 r90 bottom
R332 "R1005_R_SP" R1005_R_SP#2 198.4,116.1 r90 bottom
R333 "R1005_R_SP" R1005_R_SP#2 196,129.1 r180 bottom
R334 "R1005_R_SP" R1005_R_SP#2 196,138.35 r180 bottom
R335 "R1005_R_SP" R1005_R_SP#2 196,147.6 r180 bottom
R336 "R1005_R_SP" R1005_R_SP#2 196,156.85 r180 bottom
R337 "R1005_R_SP" R1005_R_SP#2 87,158.5 r90 bottom
R338 "R1005_R_SP" R1005_R_SP#2 87,149.25 r90 bottom
R339 "R1005_R_SP" R1005_R_SP#2 87,140 r90 bottom
R340 "R1005_R_SP" R1005_R_SP#2 87,130.75 r90 bottom
R341 "R1005_R_SP" R1005_R_SP#2 86.95,117.85 r90 bottom
R342 "R1005_R_SP" R1005_R_SP#2 86.95,108.6 r90 bottom
R343 "R1005_R_SP" R1005_R_SP#2 86.95,99.35 r90 bottom
R344 "R1005_R_SP" R1005_R_SP#2 86.95,90.1 r90 bottom
R345 "R1005_R_SP" R1005_R_SP#2 105.5,126.25 r180 bottom
R346 "R1005_R_SP" R1005_R_SP#2 114.75,126.25 r180 bottom
R347 "R1005_R_SP" R1005_R_SP#2 124,126.25 r180 bottom
R348 "R1005_R_SP" R1005_R_SP#2 133.25,126.25 r180 bottom
R349 "R1005_R_SP" R1005_R_SP#2 147.65,126.25 r180 bottom
R350 "R1005_R_SP" R1005_R_SP#2 156.9,126.25 r180 bottom
R351 "R1005_R_SP" R1005_R_SP#2 166.15,126.25 r180 bottom
R352 "R1005_R_SP" R1005_R_SP#2 175.4,126.25 r180 bottom
R353 "R1005_R_SP" R1005_R_SP#2 197,86.4 r270 bottom
R354 "R1005_R_SP" R1005_R_SP#2 197,95.65 r270 bottom
R355 "R1005_R_SP" R1005_R_SP#2 197,104.9 r270 bottom
R356 "R1005_R_SP" R1005_R_SP#2 197,114.15 r270 bottom
R357 "R1005_R_SP" R1005_R_SP#2 197,125.25 r270 bottom
R358 "R1005_R_SP" R1005_R_SP#2 197,134.5 r270 bottom
R359 "R1005_R_SP" R1005_R_SP#2 197,143.75 r270 bottom
R360 "R1005_R_SP" R1005_R_SP#2 197,153 r270 bottom
RV1 "V2125-R-SP" V2125-R-SP 99.75,156.75 r180 top
S1 "CHS-04TB-R-SP" CHS-04TB-R-SP 111,151.75 r0 top
S2 "SKHMQKE010-R-SP" SKHMQKE010-R-SP 154.5,136.5 r90 top
T2 "750342424-D-SP" 750342424-D-SP 225,43.75 r0 top
T3 "SUMIDA-PQ2620-D-SP" SUMIDA-PQ2620-D-SP 102.75,37.5 r270 top
TP1 "TP-TH1.0-L1.6-D-SP" TP-TH1.0-L1.6-D-SP 53.5,49.75 r0 top
TP2 "TP-TH1.0-L1.6-D-SP" TP-TH1.0-L1.6-D-SP 57.75,25.75 r0 top
TP3 "TP-TH1.0-L1.6-D-SP" TP-TH1.0-L1.6-D-SP 169.5,54.5 r90 top
TP4 "TP-TH1.0-L1.6-D-SP" TP-TH1.0-L1.6-D-SP 185.75,56 r270 top
TP5 "TP-TH1.0-L1.6-D-SP" TP-TH1.0-L1.6-D-SP 197.5,25 r0 top
TP6 "TP-TH1.0-L1.6-D-SP" TP-TH1.0-L1.6-D-SP 97.5,142.75 r0 top
TP7 "TP-TH1.0-L1.6-D-SP" TP-TH1.0-L1.6-D-SP 112.25,136.75 r180 top
TP8 "TP-TH1.0-L1.6-D-SP" TP-TH1.0-L1.6-D-SP 102.75,136.75 r180 top
TP9 "TP-TH1.0-L1.6-D-SP" TP-TH1.0-L1.6-D-SP 142.75,136.75 r90 top
TP10 "TP-TH1.0-L1.6-D-SP" TP-TH1.0-L1.6-D-SP 142.75,139.25 r90 top
TP11 "TP-TH1.0-L1.6-D-SP" TP-TH1.0-L1.6-D-SP 142.75,141.75 r90 top
TP12 "TP-TH1.0-L1.6-D-SP" TP-TH1.0-L1.6-D-SP 142.75,144.25 r90 top
TP13 "TP-TH1.0-L1.6-D-SP" TP-TH1.0-L1.6-D-SP 141,158 r90 top
TP14 "TP-TH1.0-L1.6-D-SP" TP-TH1.0-L1.6-D-SP 138.5,158 r90 top
TP15 "TP-TH1.0-L1.6-D-SP" TP-TH1.0-L1.6-D-SP 135.5,158.25 r90 top
TP16 "TP-TH1.0-L1.6-D-SP" TP-TH1.0-L1.6-D-SP 133,158.25 r0 top
TP17 "TP-TH1.0-L1.6-D-SP" TP-TH1.0-L1.6-D-SP 90.25,157 r180 top
TP18 "TP-TH1.0-L1.6-D-SP" TP-TH1.0-L1.6-D-SP 90.25,147.75 r180 top
TP19 "TP-TH1.0-L1.6-D-SP" TP-TH1.0-L1.6-D-SP 90.25,138.5 r180 top
TP20 "TP-TH1.0-L1.6-D-SP" TP-TH1.0-L1.6-D-SP 90.25,129.25 r180 top
TP21 "TP-TH1.0-L1.6-D-SP" TP-TH1.0-L1.6-D-SP 87,121.25 r180 top
TP22 "TP-TH1.0-L1.6-D-SP" TP-TH1.0-L1.6-D-SP 87,112 r180 top
TP23 "TP-TH1.0-L1.6-D-SP" TP-TH1.0-L1.6-D-SP 87,102.75 r180 top
TP24 "TP-TH1.0-L1.6-D-SP" TP-TH1.0-L1.6-D-SP 87,93.5 r180 top
TP25 "TP-TH1.0-L1.6-D-SP" TP-TH1.0-L1.6-D-SP 79,160.75 r180 top
TP26 "TP-TH1.0-L1.6-D-SP" TP-TH1.0-L1.6-D-SP 79,151.5 r180 top
TP27 "TP-TH1.0-L1.6-D-SP" TP-TH1.0-L1.6-D-SP 79,142.25 r180 top
TP28 "TP-TH1.0-L1.6-D-SP" TP-TH1.0-L1.6-D-SP 79,133 r180 top
TP29 "TP-TH1.0-L1.6-D-SP" TP-TH1.0-L1.6-D-SP 79,120.15 r180 top
TP30 "TP-TH1.0-L1.6-D-SP" TP-TH1.0-L1.6-D-SP 79,110.9 r180 top
TP31 "TP-TH1.0-L1.6-D-SP" TP-TH1.0-L1.6-D-SP 79,101.65 r180 top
